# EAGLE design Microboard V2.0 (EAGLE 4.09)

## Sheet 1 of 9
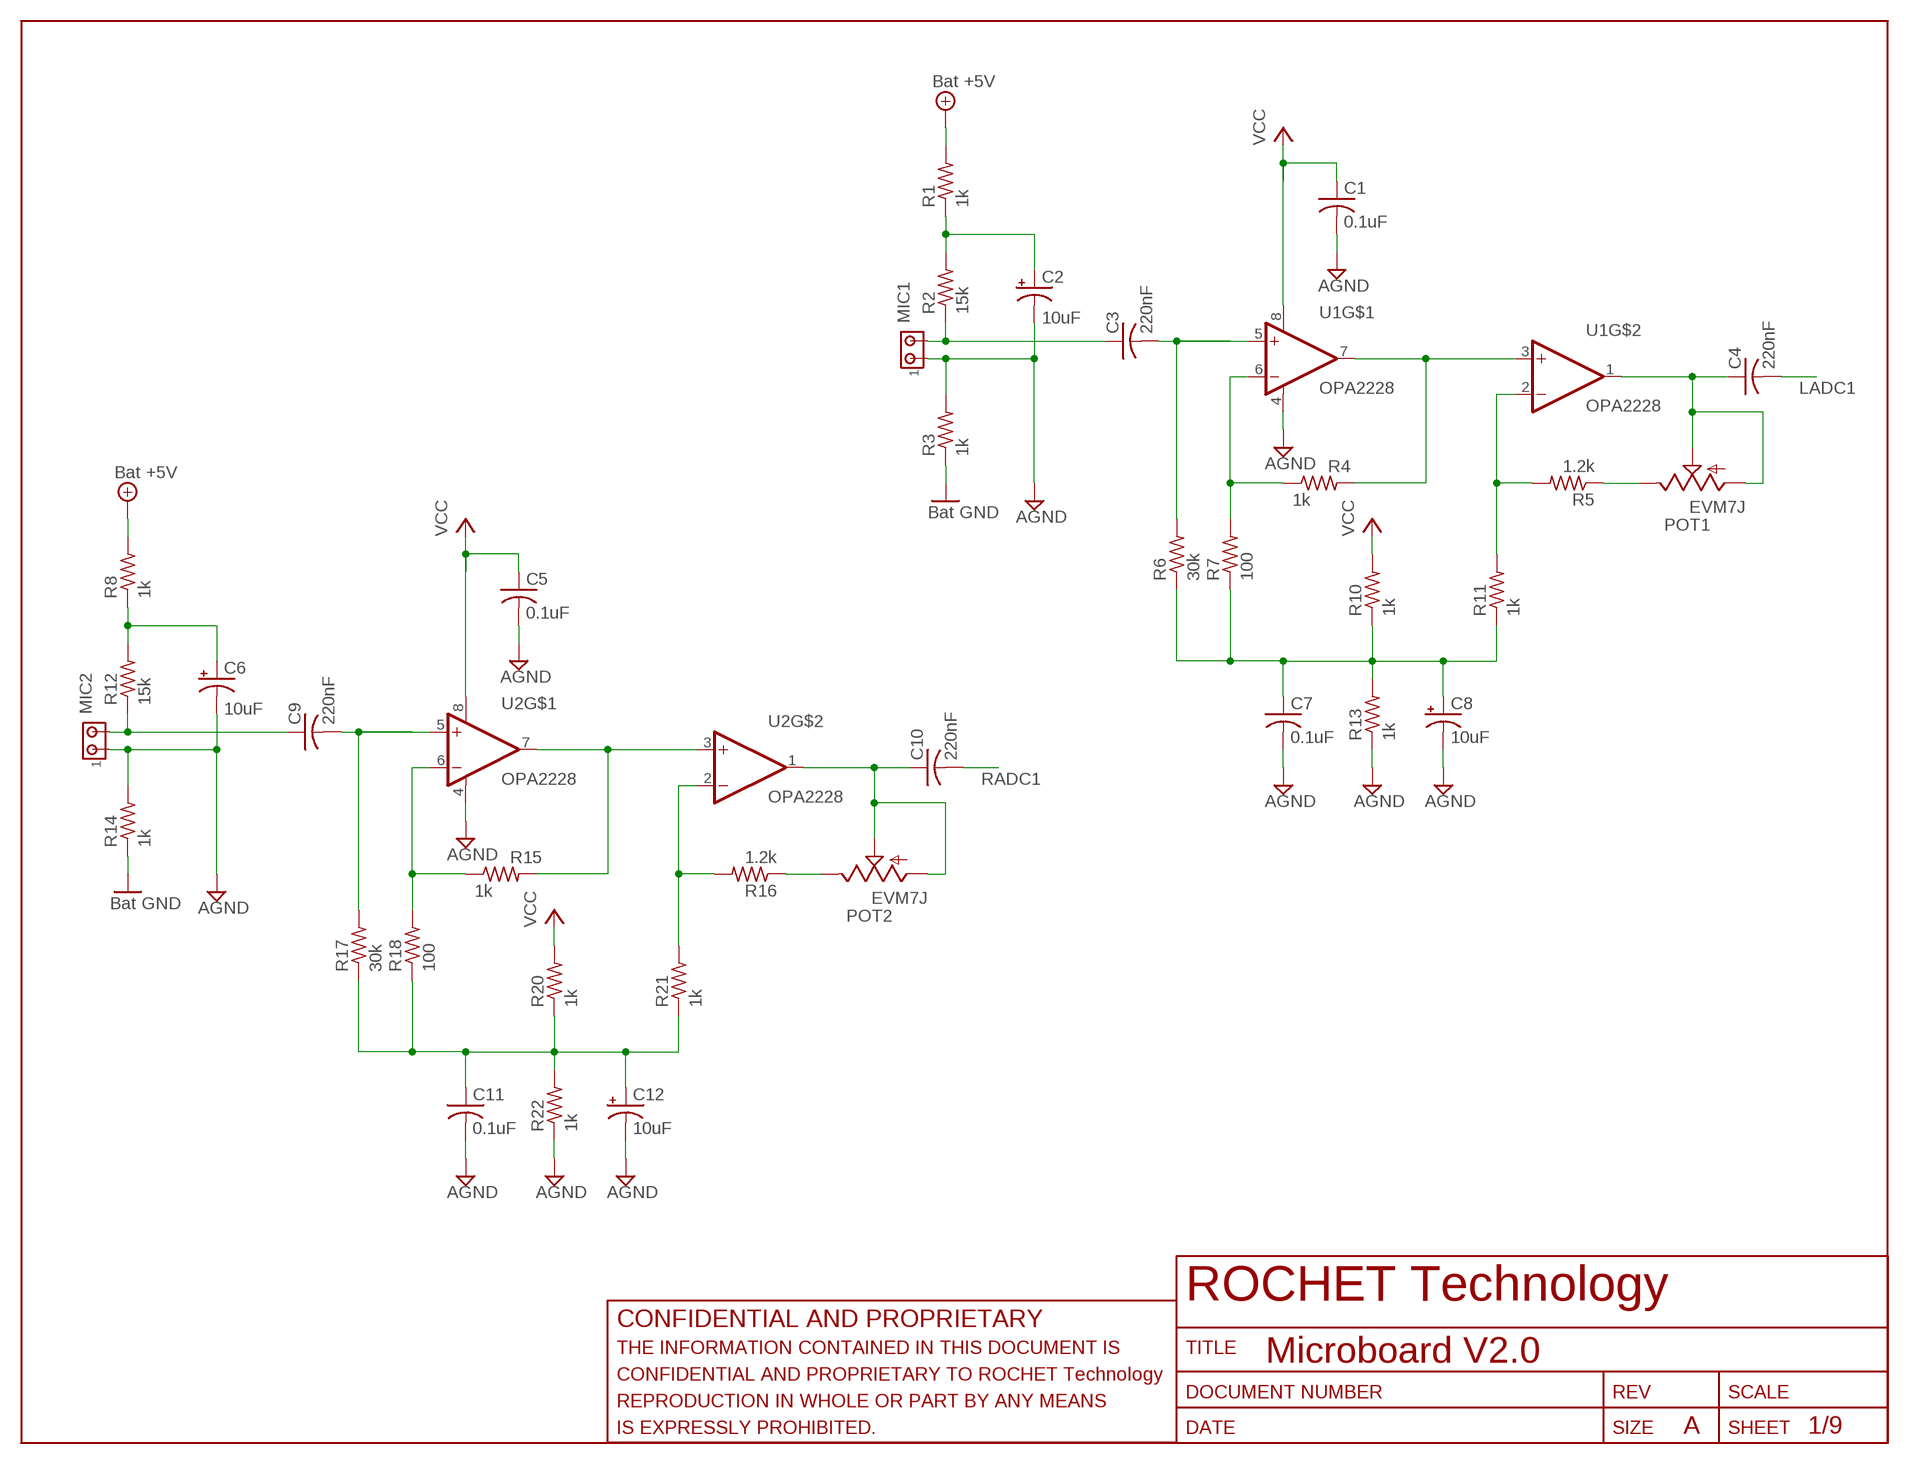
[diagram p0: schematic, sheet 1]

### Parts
C1  0.1uF  C-USC0603  [C0603]
C2  10uF  CPOL-USA/3216-18W  [A/3216-18W]
C3  220nF  C-US102-054X133  [C102-054X133]
C4  220nF  C-US102-054X133  [C102-054X133]
C5  0.1uF  C-USC0603  [C0603]
C6  10uF  CPOL-USA/3216-18W  [A/3216-18W]
C7  0.1uF  C-USC0603  [C0603]
C8  10uF  CPOL-USA/3216-18W  [A/3216-18W]
C9  220nF  C-US102-054X133  [C102-054X133]
C10  220nF  C-US102-054X133  [C102-054X133]
C11  0.1uF  C-USC0603  [C0603]
C12  10uF  CPOL-USA/3216-18W  [A/3216-18W]
MIC1  MTA02-100  [10X02MTA]
MIC2  MTA02-100  [10X02MTA]
POT1  EVM7J  P7J471CT-ND  [POT_EVM7J]
POT2  EVM7J  P7J471CT-ND  [POT_EVM7J]
R1  1k  R-US_M0805  [M0805]
R2  15k  R-US_M0805  [M0805]
R3  1k  R-US_M0805  [M0805]
R4  1k  R-US_R0805  [R0805]
R5  1.2k  R-US_R0805  [R0805]
R6  30k  R-US_R0805  [R0805]
R7  100  R-US_R0805  [R0805]
R8  1k  R-US_M0805  [M0805]
R10  1k  R-US_R0805  [R0805]
R11  1k  R-US_R0805  [R0805]
R12  15k  R-US_M0805  [M0805]
R13  1k  R-US_R0805  [R0805]
R14  1k  R-US_M0805  [M0805]
R15  1k  R-US_R0805  [R0805]
R16  1.2k  R-US_R0805  [R0805]
R17  30k  R-US_R0805  [R0805]
R18  100  R-US_R0805  [R0805]
R20  1k  R-US_R0805  [R0805]
R21  1k  R-US_R0805  [R0805]
R22  1k  R-US_R0805  [R0805]
U1  OPA2228  OPA2228SWAP  [SO-08]
U2  OPA2228  OPA2228SWAP  [SO-08]

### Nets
+5V: R1.2 R8.2 ; supply symbol labelled Bat +5V ; also sheet 3,5,7,9
AGND: C1.2 C2.- C5.2 C6.- C7.2 C8.- C11.2 C12.- MIC1.1 MIC2.1 R3.2 R13.1 R14.2 R22.1 U1.4(V-) U2.4(V-) ; also sheet 2,3,4,5,6,7,8,9
GND: R3.1 R14.1 ; supply symbol labelled Bat GND ; also sheet 3,5,7,9
LADC1: C4.2 ; also sheet 2
N$1: C9.1 MIC2.2 R12.1
N$2: C3.1 MIC1.2 R2.1
N$3: C9.2 R17.2 U2.5(+IN)
N$4: C3.2 R6.2 U1.5(+IN)
N$5: C11.1 C12.+ R17.1 R18.1 R20.1 R21.1 R22.2
N$6: C7.1 C8.+ R6.1 R7.1 R10.1 R11.1 R13.2
N$7: R15.1 R18.2 U2.6(-IN)
N$8: R15.2 U2.3(+IN) U2.7(OUT)
N$9: R16.2 R21.2 U2.2(-IN)
N$10: R4.1 R7.2 U1.6(-IN)
N$11: POT1.P$3(C) R5.1
N$12: R4.2 U1.3(+IN) U1.7(OUT)
N$13: R5.2 R11.2 U1.2(-IN)
N$15: C2.+ R1.1 R2.2
N$38: POT2.P$3(C) R16.1
N$58: C10.1 POT2.P$1(A) POT2.P$2(B) U2.1(OUT)
N$77: C4.1 POT1.P$1(A) POT1.P$2(B) U1.1(OUT)
N$78: C6.+ R8.1 R12.2
RADC1: C10.2 ; also sheet 2
VCC: C1.1 C5.1 R10.2 R20.2 U1.8(V+) U2.8(V+) ; also sheet 2,3,4,5,6,7,8,9

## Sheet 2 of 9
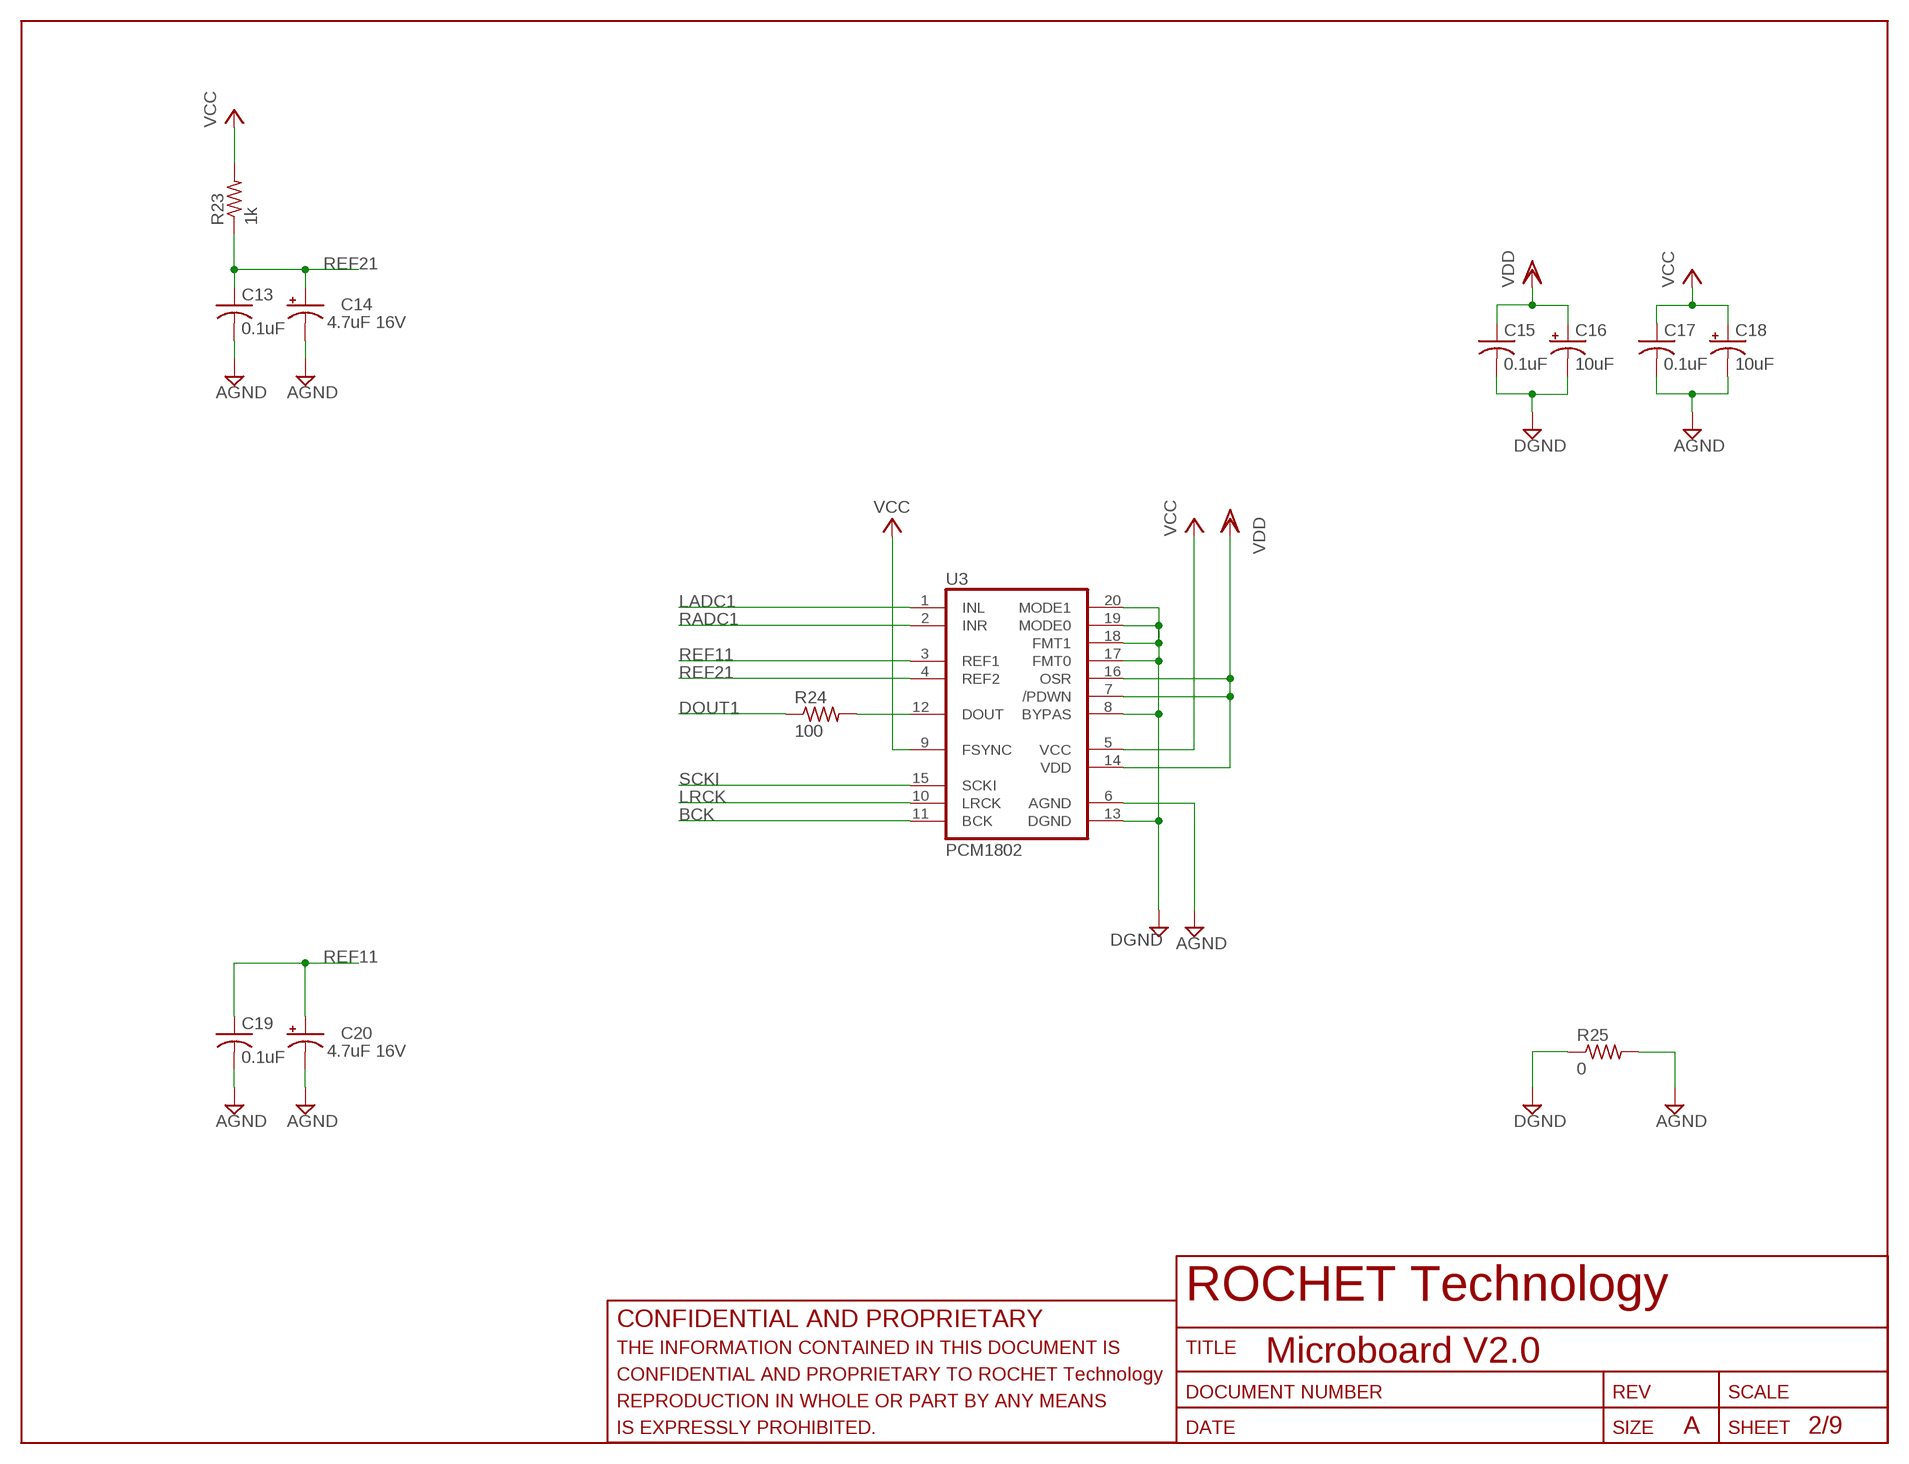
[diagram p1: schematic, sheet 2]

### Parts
C13  0.1uF  C-USC0603  [C0603]
C14  4.7uF 16V  CPOL-USA/3216-18W  [A/3216-18W]
C15  0.1uF  C-USC0603  [C0603]
C16  10uF  CPOL-USA/3216-18W  [A/3216-18W]
C17  0.1uF  C-USC0603  [C0603]
C18  10uF  CPOL-USA/3216-18W  [A/3216-18W]
C19  0.1uF  C-USC0603  [C0603]
C20  4.7uF 16V  CPOL-USA/3216-18W  [A/3216-18W]
R23  1k  R-US_R0805  [R0805]
R24  100  R-US_R0805  [R0805]
R25  0  R-US_R0805  [R0805]
U3  PCM1802  [SSOP20BU]

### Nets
AGND: C13.2 C14.- C17.2 C18.- C19.2 C20.- R25.2 U3.6(AGND) ; also sheet 1,3,4,5,6,7,8,9
BCK: U3.11(BCK) ; also sheet 4,6,8,9
DGND: C15.2 C16.- R25.1 U3.8(BYPAS) U3.13(DGND) U3.17(FMT0) U3.18(FMT1) U3.19(MODE0) U3.20(MODE1) ; also sheet 4,6,8,9
DOUT1: R24.1 ; also sheet 9
LADC1: U3.1(INL) ; also sheet 1
LRCK: U3.10(LRCK) ; also sheet 4,6,8,9
N$22: R24.2 U3.12(DOUT)
RADC1: U3.2(INR) ; also sheet 1
REF11: C19.1 C20.+ U3.3(REF1)
REF21: C13.1 C14.+ R23.1 U3.4(REF2)
SCKI: U3.15(SCKI) ; also sheet 4,6,8,9
VCC: C17.1 C18.+ R23.2 U3.5(VCC) U3.9(FSYNC) ; also sheet 1,3,4,5,6,7,8,9
VDD: C15.1 C16.+ U3.7(/PDWN) U3.14(VDD) U3.16(OSR) ; also sheet 4,6,8,9

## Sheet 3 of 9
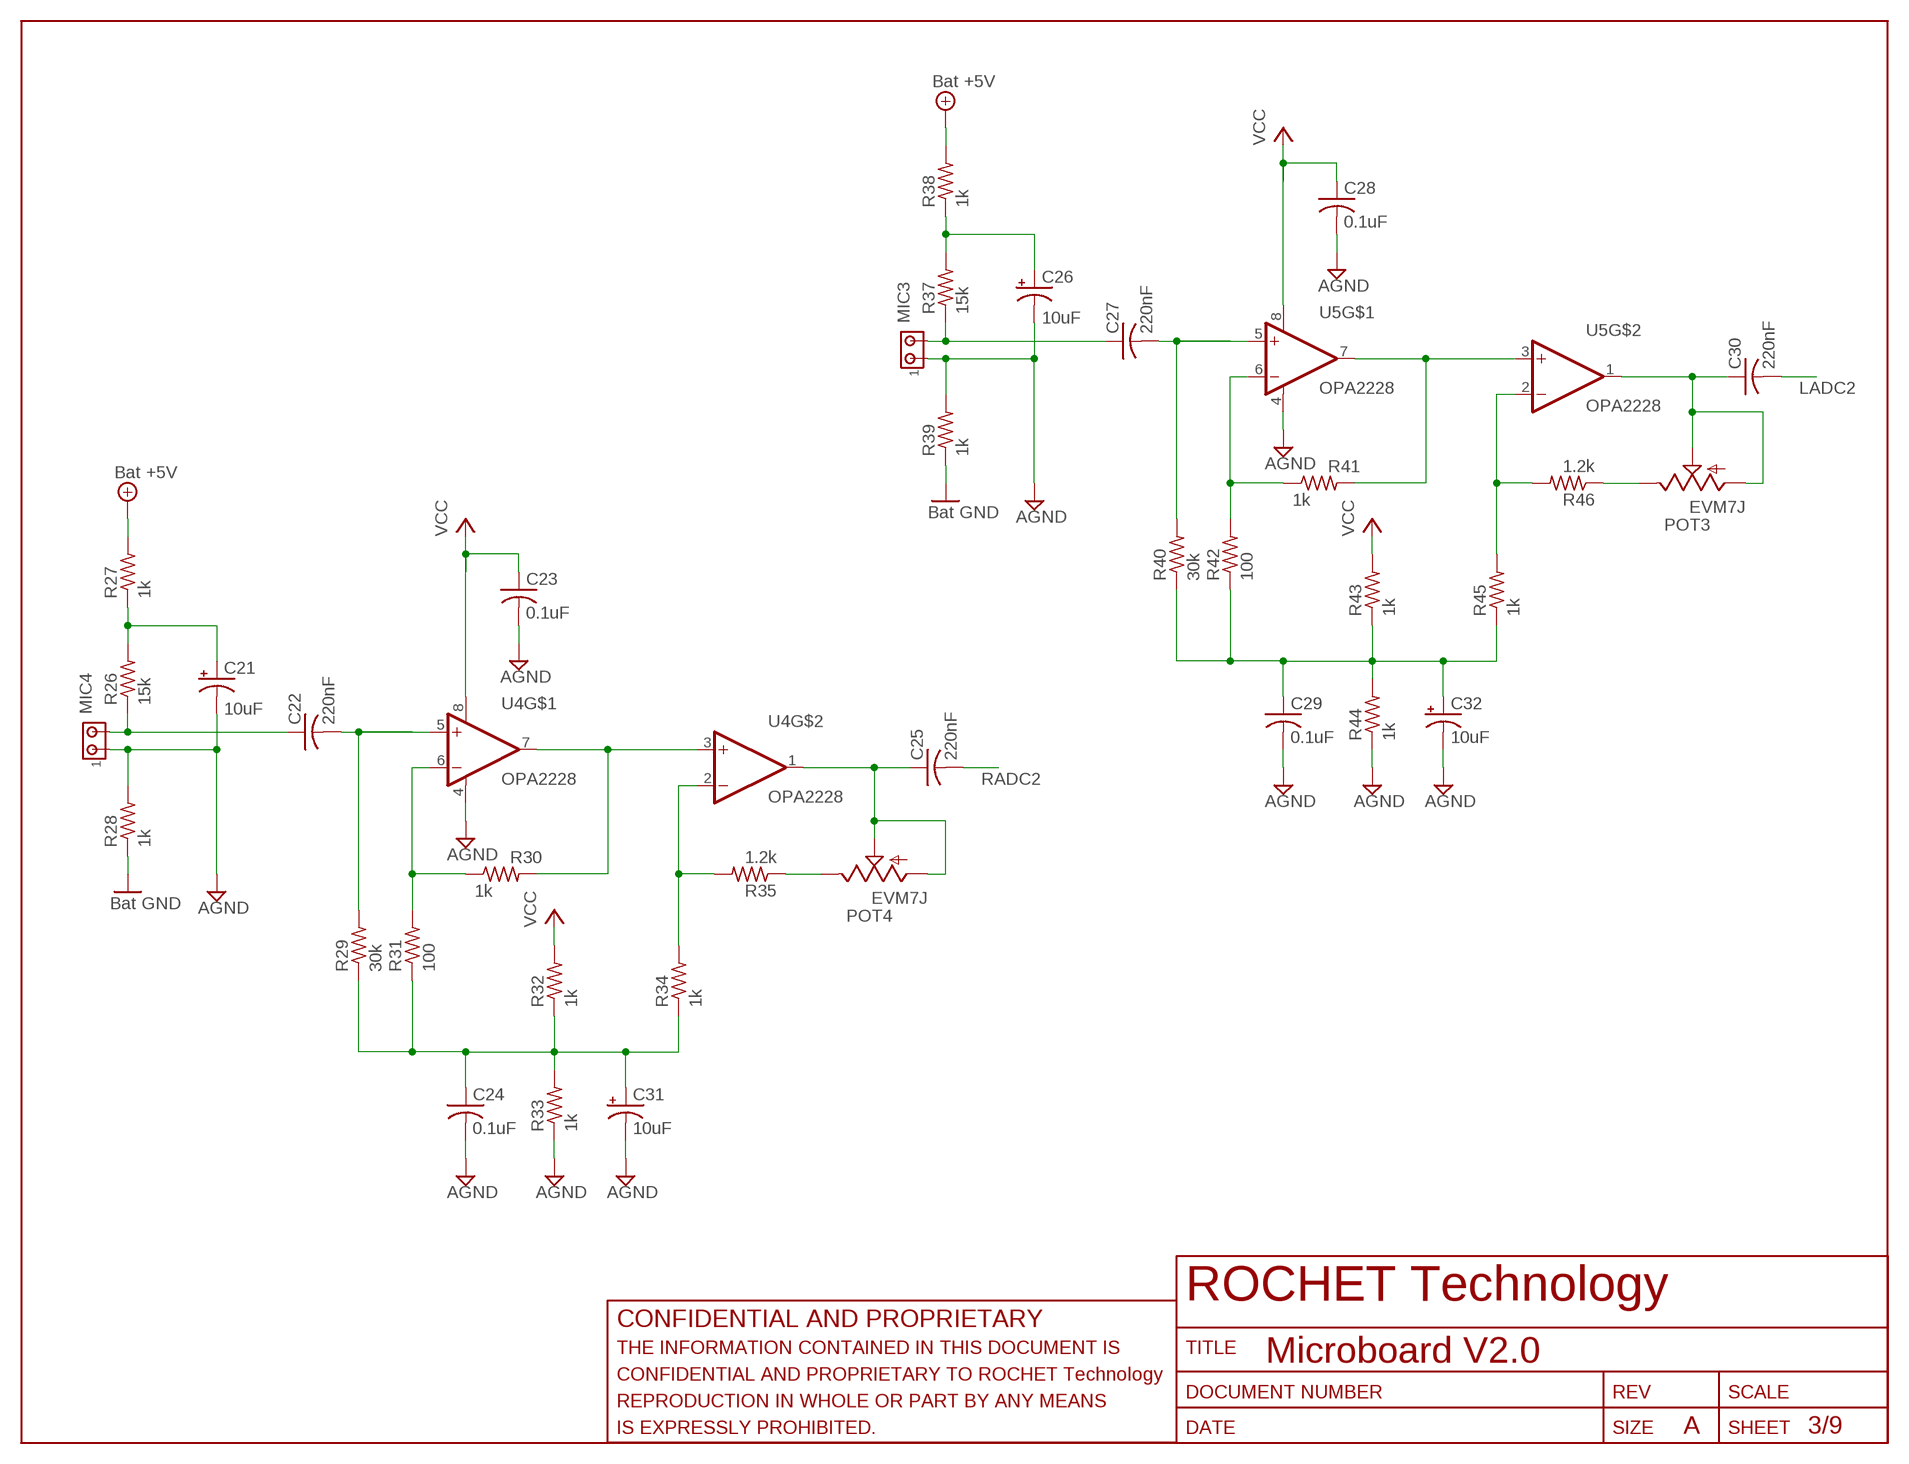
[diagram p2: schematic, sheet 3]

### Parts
C21  10uF  CPOL-USA/3216-18W  [A/3216-18W]
C22  220nF  C-US102-054X133  [C102-054X133]
C23  0.1uF  C-USC0603  [C0603]
C24  0.1uF  C-USC0603  [C0603]
C25  220nF  C-US102-054X133  [C102-054X133]
C26  10uF  CPOL-USA/3216-18W  [A/3216-18W]
C27  220nF  C-US102-054X133  [C102-054X133]
C28  0.1uF  C-USC0603  [C0603]
C29  0.1uF  C-USC0603  [C0603]
C30  220nF  C-US102-054X133  [C102-054X133]
C31  10uF  CPOL-USA/3216-18W  [A/3216-18W]
C32  10uF  CPOL-USA/3216-18W  [A/3216-18W]
MIC3  MTA02-100  [10X02MTA]
MIC4  MTA02-100  [10X02MTA]
POT3  EVM7J  P7J471CT-ND  [POT_EVM7J]
POT4  EVM7J  P7J471CT-ND  [POT_EVM7J]
R26  15k  R-US_M0805  [M0805]
R27  1k  R-US_M0805  [M0805]
R28  1k  R-US_M0805  [M0805]
R29  30k  R-US_R0805  [R0805]
R30  1k  R-US_R0805  [R0805]
R31  100  R-US_R0805  [R0805]
R32  1k  R-US_R0805  [R0805]
R33  1k  R-US_R0805  [R0805]
R34  1k  R-US_R0805  [R0805]
R35  1.2k  R-US_R0805  [R0805]
R37  15k  R-US_M0805  [M0805]
R38  1k  R-US_M0805  [M0805]
R39  1k  R-US_M0805  [M0805]
R40  30k  R-US_R0805  [R0805]
R41  1k  R-US_R0805  [R0805]
R42  100  R-US_R0805  [R0805]
R43  1k  R-US_R0805  [R0805]
R44  1k  R-US_R0805  [R0805]
R45  1k  R-US_R0805  [R0805]
R46  1.2k  R-US_R0805  [R0805]
U4  OPA2228  OPA2228SWAP  [SO-08]
U5  OPA2228  OPA2228SWAP  [SO-08]

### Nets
+5V: R27.2 R38.2 ; supply symbol labelled Bat +5V ; also sheet 1,5,7,9
AGND: C21.- C23.2 C24.2 C26.- C28.2 C29.2 C31.- C32.- MIC3.1 MIC4.1 R28.2 R33.1 R39.2 R44.1 U4.4(V-) U5.4(V-) ; also sheet 1,2,4,5,6,7,8,9
GND: R28.1 R39.1 ; supply symbol labelled Bat GND ; also sheet 1,5,7,9
LADC2: C30.2 ; also sheet 4
N$14: POT4.P$3(C) R35.1
N$16: C22.1 MIC4.2 R26.1
N$18: C22.2 R29.2 U4.5(+IN)
N$19: C24.1 C31.+ R29.1 R31.1 R32.1 R33.2 R34.1
N$21: R30.1 R31.2 U4.6(-IN)
N$23: R30.2 U4.3(+IN) U4.7(OUT)
N$24: R34.2 R35.2 U4.2(-IN)
N$25: POT3.P$3(C) R46.1
N$26: C21.+ R26.2 R27.1
N$27: C27.1 MIC3.2 R37.1
N$28: C27.2 R40.2 U5.5(+IN)
N$29: C29.1 C32.+ R40.1 R42.1 R43.1 R44.2 R45.1
N$30: R41.1 R42.2 U5.6(-IN)
N$31: R41.2 U5.3(+IN) U5.7(OUT)
N$32: R45.2 R46.2 U5.2(-IN)
N$34: C26.+ R37.2 R38.1
N$81: C25.1 POT4.P$1(A) POT4.P$2(B) U4.1(OUT)
N$82: C30.1 POT3.P$1(A) POT3.P$2(B) U5.1(OUT)
RADC2: C25.2 ; also sheet 4
VCC: C23.1 C28.1 R32.2 R43.2 U4.8(V+) U5.8(V+) ; also sheet 1,2,4,5,6,7,8,9

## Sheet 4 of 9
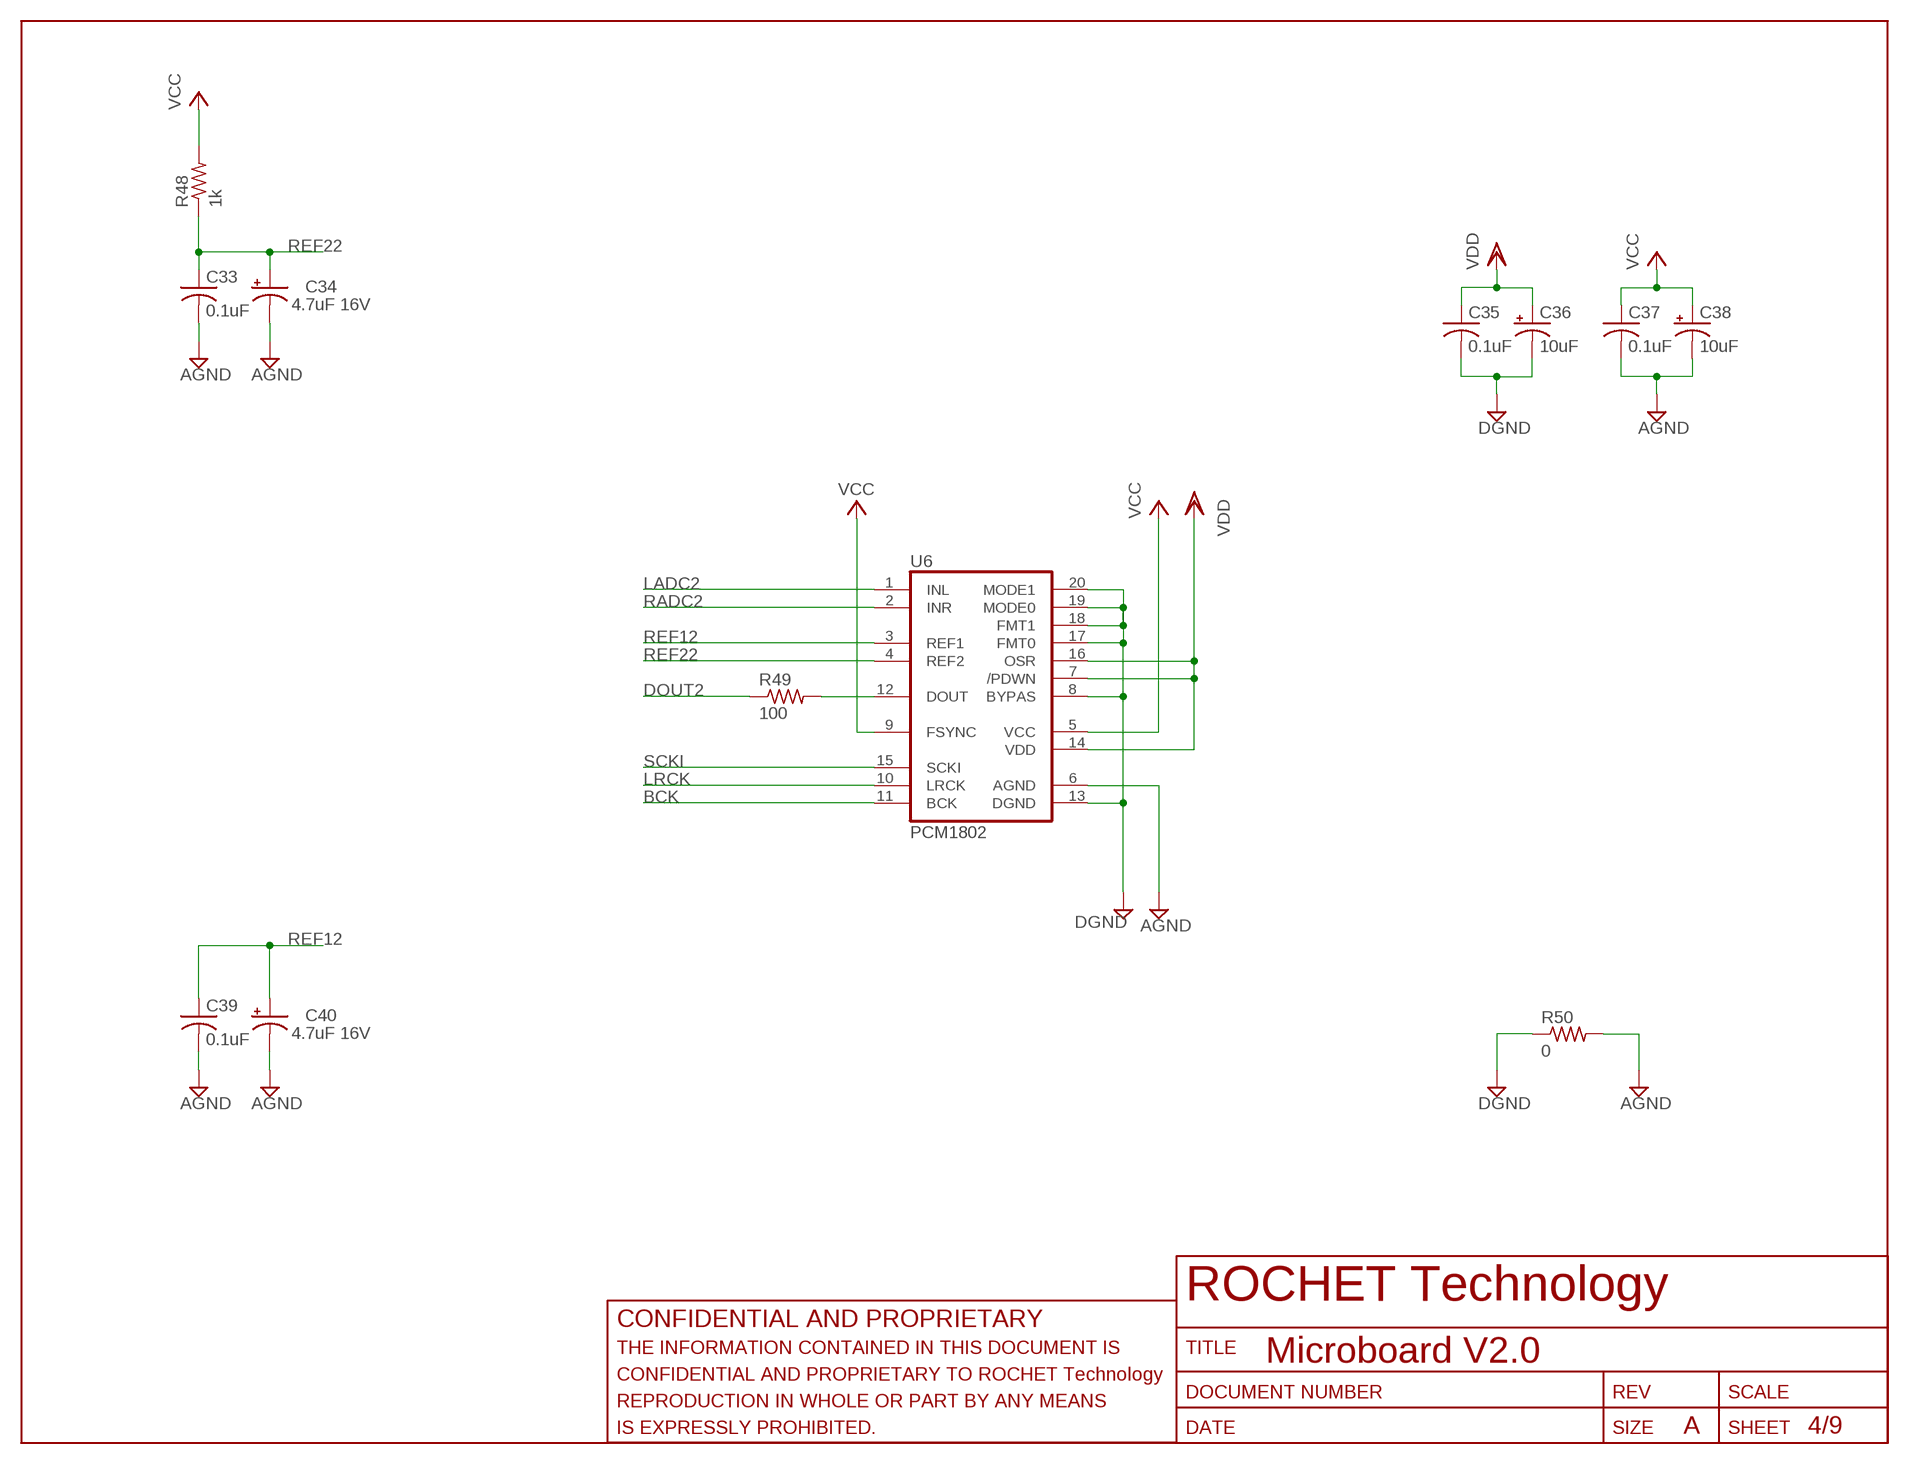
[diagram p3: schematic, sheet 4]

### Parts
C33  0.1uF  C-USC0603  [C0603]
C34  4.7uF 16V  CPOL-USA/3216-18W  [A/3216-18W]
C35  0.1uF  C-USC0603  [C0603]
C36  10uF  CPOL-USA/3216-18W  [A/3216-18W]
C37  0.1uF  C-USC0603  [C0603]
C38  10uF  CPOL-USA/3216-18W  [A/3216-18W]
C39  0.1uF  C-USC0603  [C0603]
C40  4.7uF 16V  CPOL-USA/3216-18W  [A/3216-18W]
R48  1k  R-US_R0805  [R0805]
R49  100  R-US_R0805  [R0805]
R50  0  R-US_R0805  [R0805]
U6  PCM1802  [SSOP20BU]

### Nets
AGND: C33.2 C34.- C37.2 C38.- C39.2 C40.- R50.2 U6.6(AGND) ; also sheet 1,2,3,5,6,7,8,9
BCK: U6.11(BCK) ; also sheet 2,6,8,9
DGND: C35.2 C36.- R50.1 U6.8(BYPAS) U6.13(DGND) U6.17(FMT0) U6.18(FMT1) U6.19(MODE0) U6.20(MODE1) ; also sheet 2,6,8,9
DOUT2: R49.1 ; also sheet 9
LADC2: U6.1(INL) ; also sheet 3
LRCK: U6.10(LRCK) ; also sheet 2,6,8,9
N$17: R49.2 U6.12(DOUT)
RADC2: U6.2(INR) ; also sheet 3
REF12: C39.1 C40.+ U6.3(REF1)
REF22: C33.1 C34.+ R48.1 U6.4(REF2)
SCKI: U6.15(SCKI) ; also sheet 2,6,8,9
VCC: C37.1 C38.+ R48.2 U6.5(VCC) U6.9(FSYNC) ; also sheet 1,2,3,5,6,7,8,9
VDD: C35.1 C36.+ U6.7(/PDWN) U6.14(VDD) U6.16(OSR) ; also sheet 2,6,8,9

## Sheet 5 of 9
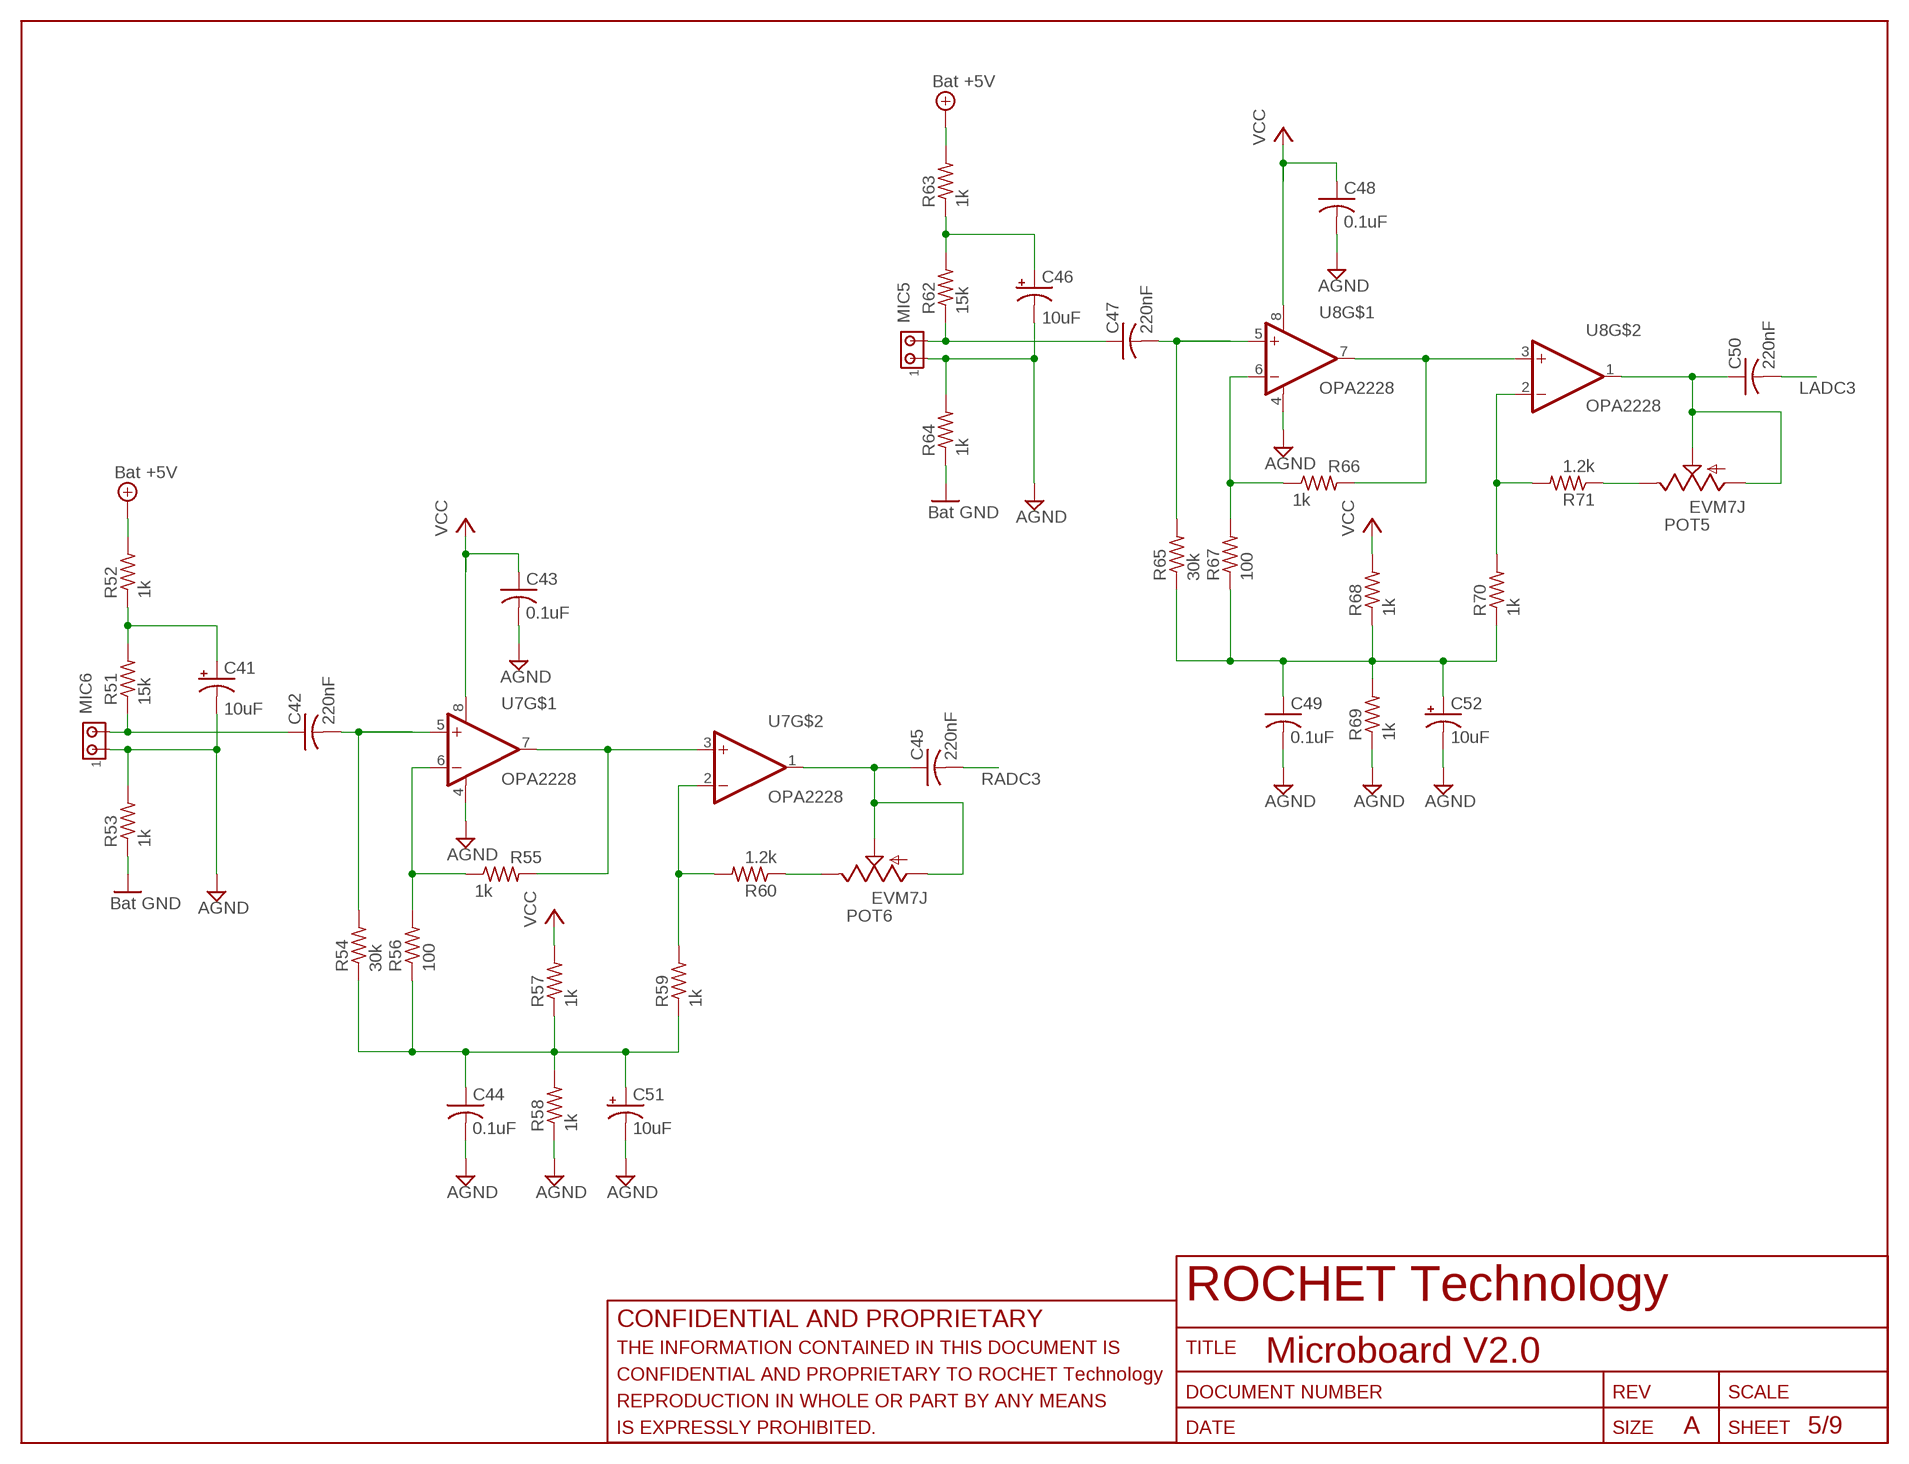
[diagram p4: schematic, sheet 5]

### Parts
C41  10uF  CPOL-USA/3216-18W  [A/3216-18W]
C42  220nF  C-US102-054X133  [C102-054X133]
C43  0.1uF  C-USC0603  [C0603]
C44  0.1uF  C-USC0603  [C0603]
C45  220nF  C-US102-054X133  [C102-054X133]
C46  10uF  CPOL-USA/3216-18W  [A/3216-18W]
C47  220nF  C-US102-054X133  [C102-054X133]
C48  0.1uF  C-USC0603  [C0603]
C49  0.1uF  C-USC0603  [C0603]
C50  220nF  C-US102-054X133  [C102-054X133]
C51  10uF  CPOL-USA/3216-18W  [A/3216-18W]
C52  10uF  CPOL-USA/3216-18W  [A/3216-18W]
MIC5  MTA02-100  [10X02MTA]
MIC6  MTA02-100  [10X02MTA]
POT5  EVM7J  P7J471CT-ND  [POT_EVM7J]
POT6  EVM7J  P7J471CT-ND  [POT_EVM7J]
R51  15k  R-US_M0805  [M0805]
R52  1k  R-US_M0805  [M0805]
R53  1k  R-US_M0805  [M0805]
R54  30k  R-US_R0805  [R0805]
R55  1k  R-US_R0805  [R0805]
R56  100  R-US_R0805  [R0805]
R57  1k  R-US_R0805  [R0805]
R58  1k  R-US_R0805  [R0805]
R59  1k  R-US_R0805  [R0805]
R60  1.2k  R-US_R0805  [R0805]
R62  15k  R-US_M0805  [M0805]
R63  1k  R-US_M0805  [M0805]
R64  1k  R-US_M0805  [M0805]
R65  30k  R-US_R0805  [R0805]
R66  1k  R-US_R0805  [R0805]
R67  100  R-US_R0805  [R0805]
R68  1k  R-US_R0805  [R0805]
R69  1k  R-US_R0805  [R0805]
R70  1k  R-US_R0805  [R0805]
R71  1.2k  R-US_R0805  [R0805]
U7  OPA2228  OPA2228SWAP  [SO-08]
U8  OPA2228  OPA2228SWAP  [SO-08]

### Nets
+5V: R52.2 R63.2 ; supply symbol labelled Bat +5V ; also sheet 1,3,7,9
AGND: C41.- C43.2 C44.2 C46.- C48.2 C49.2 C51.- C52.- MIC5.1 MIC6.1 R53.2 R58.1 R64.2 R69.1 U7.4(V-) U8.4(V-) ; also sheet 1,2,3,4,6,7,8,9
GND: R53.1 R64.1 ; supply symbol labelled Bat GND ; also sheet 1,3,7,9
LADC3: C50.2 ; also sheet 6
N$33: POT6.P$3(C) R60.1
N$39: C42.1 MIC6.2 R51.1
N$40: C42.2 R54.2 U7.5(+IN)
N$41: C44.1 C51.+ R54.1 R56.1 R57.1 R58.2 R59.1
N$42: R55.1 R56.2 U7.6(-IN)
N$43: R55.2 U7.3(+IN) U7.7(OUT)
N$44: R59.2 R60.2 U7.2(-IN)
N$45: POT5.P$3(C) R71.1
N$46: C41.+ R51.2 R52.1
N$47: C47.1 MIC5.2 R62.1
N$48: C47.2 R65.2 U8.5(+IN)
N$49: C49.1 C52.+ R65.1 R67.1 R68.1 R69.2 R70.1
N$50: R66.1 R67.2 U8.6(-IN)
N$51: R66.2 U8.3(+IN) U8.7(OUT)
N$52: R70.2 R71.2 U8.2(-IN)
N$54: C46.+ R62.2 R63.1
N$83: C45.1 POT6.P$1(A) POT6.P$2(B) U7.1(OUT)
N$84: C50.1 POT5.P$1(A) POT5.P$2(B) U8.1(OUT)
RADC3: C45.2 ; also sheet 6
VCC: C43.1 C48.1 R57.2 R68.2 U7.8(V+) U8.8(V+) ; also sheet 1,2,3,4,6,7,8,9

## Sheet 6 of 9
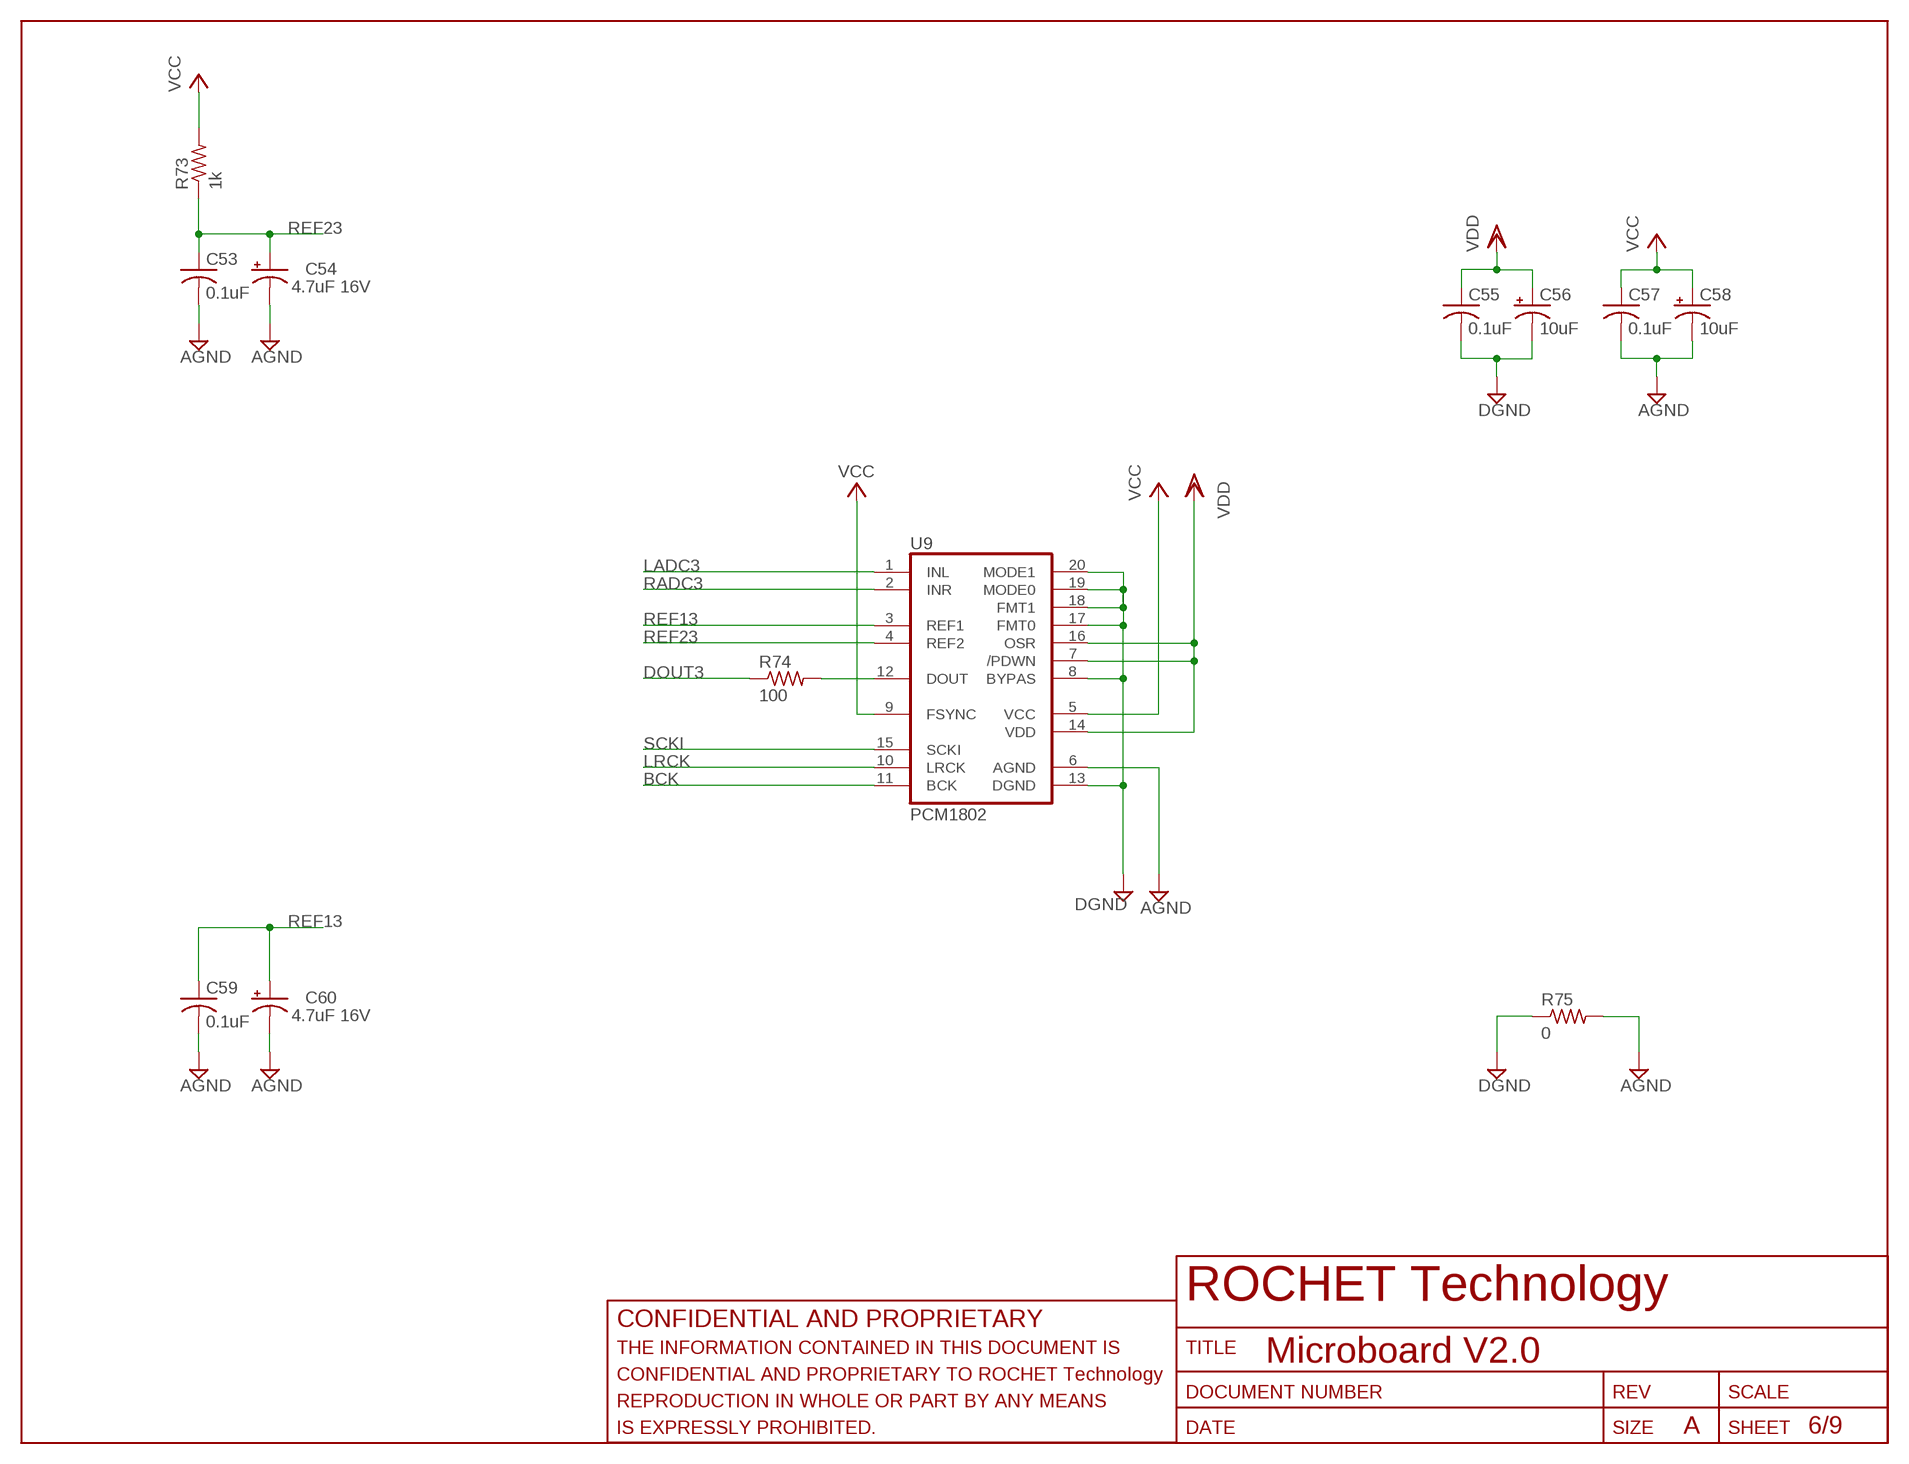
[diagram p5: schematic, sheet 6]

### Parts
C53  0.1uF  C-USC0603  [C0603]
C54  4.7uF 16V  CPOL-USA/3216-18W  [A/3216-18W]
C55  0.1uF  C-USC0603  [C0603]
C56  10uF  CPOL-USA/3216-18W  [A/3216-18W]
C57  0.1uF  C-USC0603  [C0603]
C58  10uF  CPOL-USA/3216-18W  [A/3216-18W]
C59  0.1uF  C-USC0603  [C0603]
C60  4.7uF 16V  CPOL-USA/3216-18W  [A/3216-18W]
R73  1k  R-US_R0805  [R0805]
R74  100  R-US_R0805  [R0805]
R75  0  R-US_R0805  [R0805]
U9  PCM1802  [SSOP20BU]

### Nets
AGND: C53.2 C54.- C57.2 C58.- C59.2 C60.- R75.2 U9.6(AGND) ; also sheet 1,2,3,4,5,7,8,9
BCK: U9.11(BCK) ; also sheet 2,4,8,9
DGND: C55.2 C56.- R75.1 U9.8(BYPAS) U9.13(DGND) U9.17(FMT0) U9.18(FMT1) U9.19(MODE0) U9.20(MODE1) ; also sheet 2,4,8,9
DOUT3: R74.1 ; also sheet 9
LADC3: U9.1(INL) ; also sheet 5
LRCK: U9.10(LRCK) ; also sheet 2,4,8,9
N$20: R74.2 U9.12(DOUT)
RADC3: U9.2(INR) ; also sheet 5
REF13: C59.1 C60.+ U9.3(REF1)
REF23: C53.1 C54.+ R73.1 U9.4(REF2)
SCKI: U9.15(SCKI) ; also sheet 2,4,8,9
VCC: C57.1 C58.+ R73.2 U9.5(VCC) U9.9(FSYNC) ; also sheet 1,2,3,4,5,7,8,9
VDD: C55.1 C56.+ U9.7(/PDWN) U9.14(VDD) U9.16(OSR) ; also sheet 2,4,8,9

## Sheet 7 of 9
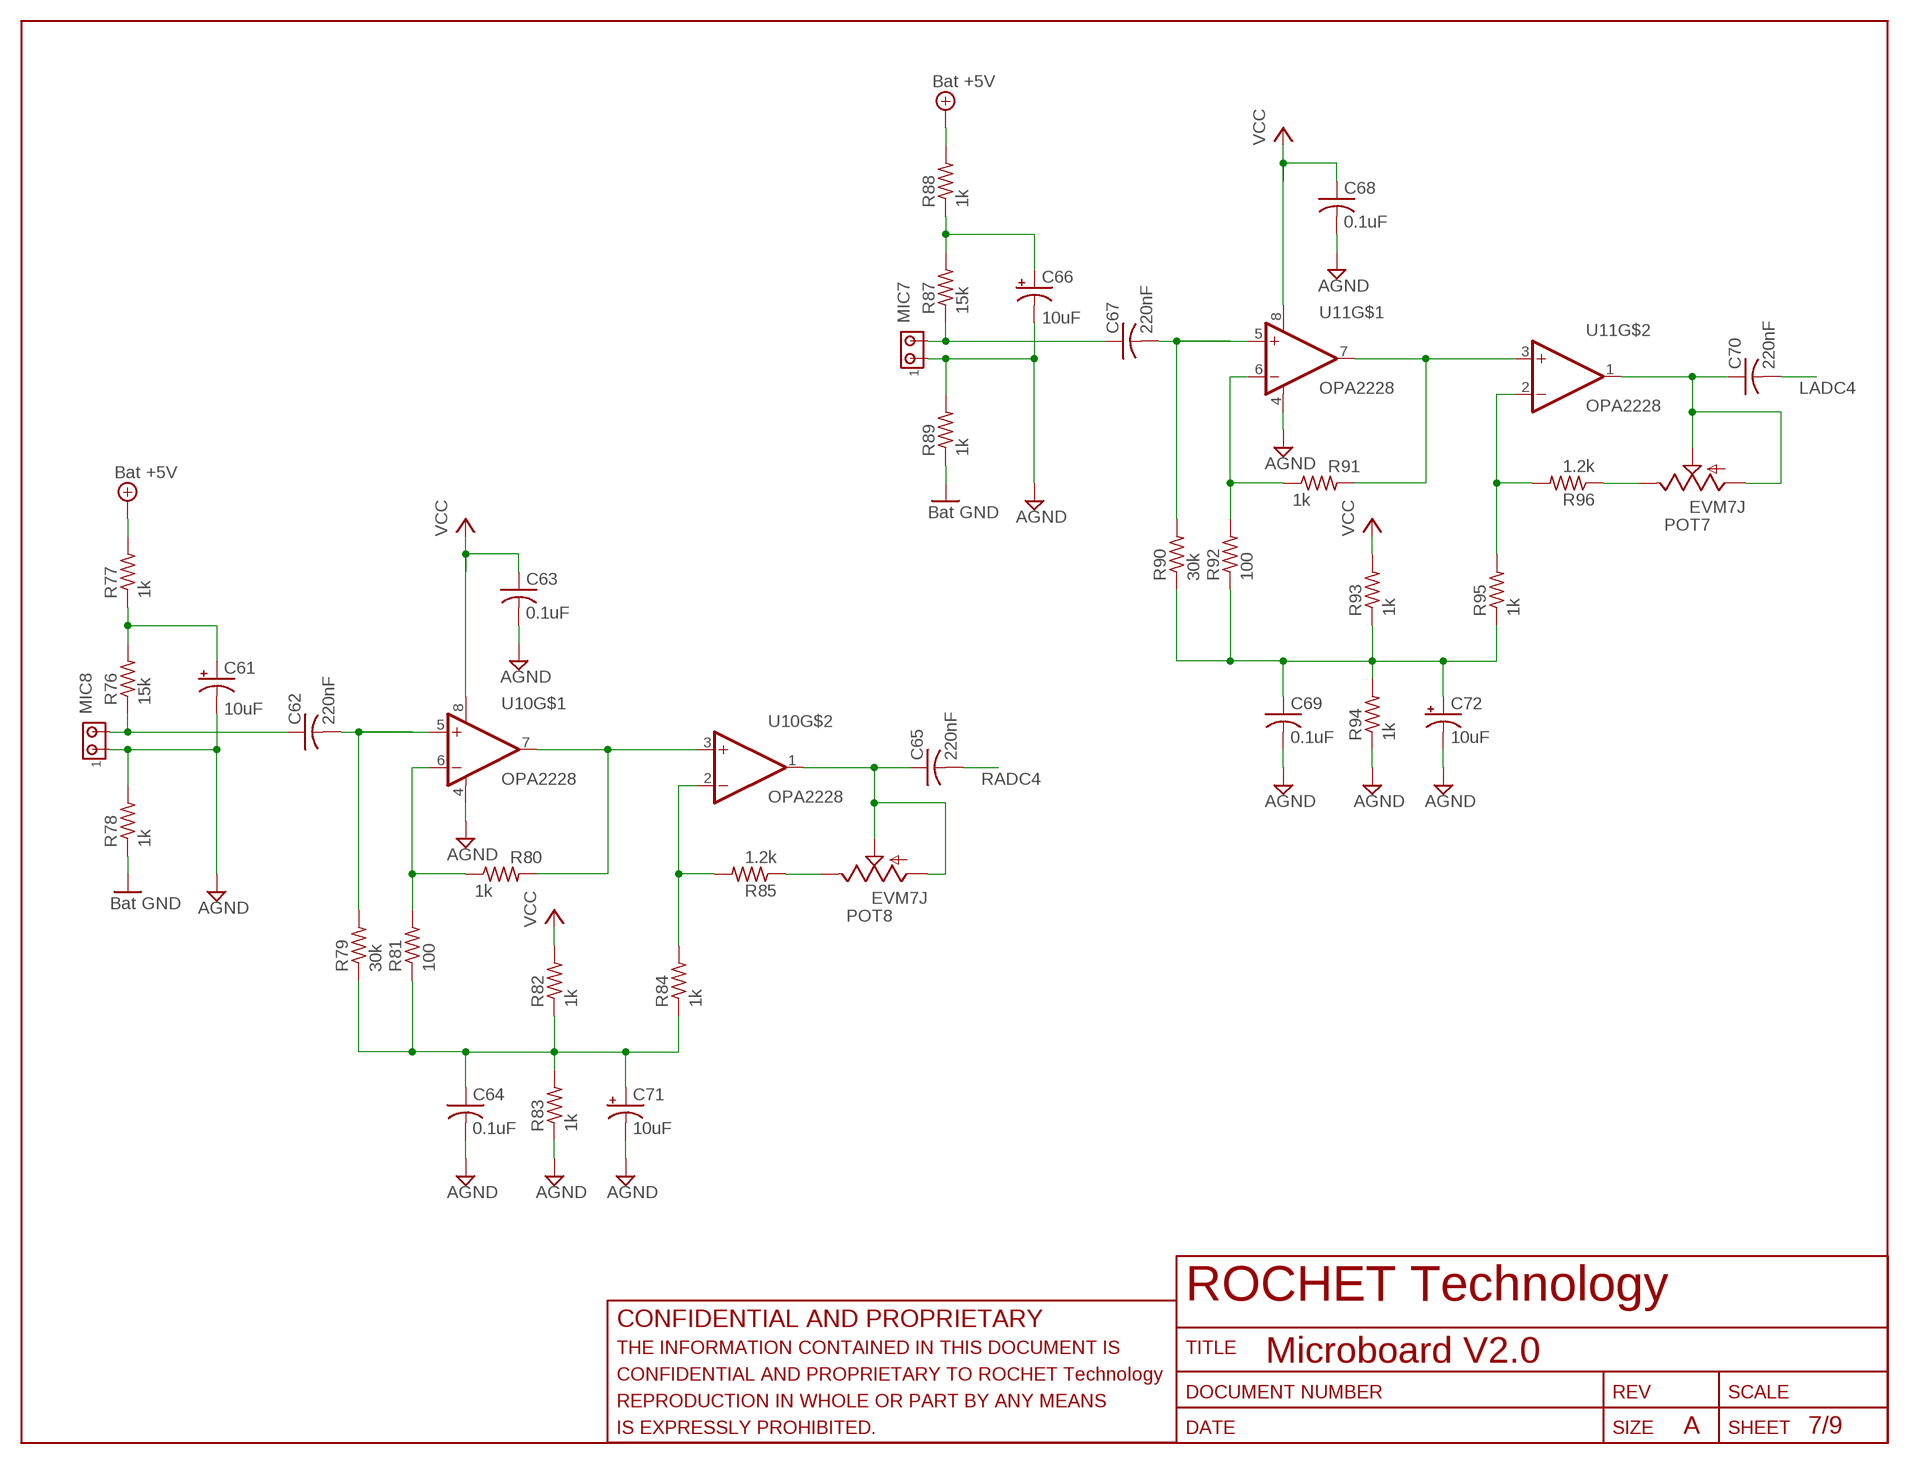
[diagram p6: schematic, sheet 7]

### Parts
C61  10uF  CPOL-USA/3216-18W  [A/3216-18W]
C62  220nF  C-US102-054X133  [C102-054X133]
C63  0.1uF  C-USC0603  [C0603]
C64  0.1uF  C-USC0603  [C0603]
C65  220nF  C-US102-054X133  [C102-054X133]
C66  10uF  CPOL-USA/3216-18W  [A/3216-18W]
C67  220nF  C-US102-054X133  [C102-054X133]
C68  0.1uF  C-USC0603  [C0603]
C69  0.1uF  C-USC0603  [C0603]
C70  220nF  C-US102-054X133  [C102-054X133]
C71  10uF  CPOL-USA/3216-18W  [A/3216-18W]
C72  10uF  CPOL-USA/3216-18W  [A/3216-18W]
MIC7  MTA02-100  [10X02MTA]
MIC8  MTA02-100  [10X02MTA]
POT7  EVM7J  P7J471CT-ND  [POT_EVM7J]
POT8  EVM7J  P7J471CT-ND  [POT_EVM7J]
R76  15k  R-US_M0805  [M0805]
R77  1k  R-US_M0805  [M0805]
R78  1k  R-US_M0805  [M0805]
R79  30k  R-US_R0805  [R0805]
R80  1k  R-US_R0805  [R0805]
R81  100  R-US_R0805  [R0805]
R82  1k  R-US_R0805  [R0805]
R83  1k  R-US_R0805  [R0805]
R84  1k  R-US_R0805  [R0805]
R85  1.2k  R-US_R0805  [R0805]
R87  15k  R-US_M0805  [M0805]
R88  1k  R-US_M0805  [M0805]
R89  1k  R-US_M0805  [M0805]
R90  30k  R-US_R0805  [R0805]
R91  1k  R-US_R0805  [R0805]
R92  100  R-US_R0805  [R0805]
R93  1k  R-US_R0805  [R0805]
R94  1k  R-US_R0805  [R0805]
R95  1k  R-US_R0805  [R0805]
R96  1.2k  R-US_R0805  [R0805]
U10  OPA2228  OPA2228SWAP  [SO-08]
U11  OPA2228  OPA2228SWAP  [SO-08]

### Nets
+5V: R77.2 R88.2 ; supply symbol labelled Bat +5V ; also sheet 1,3,5,9
AGND: C61.- C63.2 C64.2 C66.- C68.2 C69.2 C71.- C72.- MIC7.1 MIC8.1 R78.2 R83.1 R89.2 R94.1 U10.4(V-) U11.4(V-) ; also sheet 1,2,3,4,5,6,8,9
GND: R78.1 R89.1 ; supply symbol labelled Bat GND ; also sheet 1,3,5,9
LADC4: C70.2 ; also sheet 8
N$53: POT8.P$3(C) R85.1
N$59: C62.1 MIC8.2 R76.1
N$60: C62.2 R79.2 U10.5(+IN)
N$61: C64.1 C71.+ R79.1 R81.1 R82.1 R83.2 R84.1
N$62: R80.1 R81.2 U10.6(-IN)
N$63: R80.2 U10.3(+IN) U10.7(OUT)
N$64: R84.2 R85.2 U10.2(-IN)
N$66: C61.+ R76.2 R77.1
N$67: C67.1 MIC7.2 R87.1
N$68: C67.2 R90.2 U11.5(+IN)
N$69: C69.1 C72.+ R90.1 R92.1 R93.1 R94.2 R95.1
N$70: R91.1 R92.2 U11.6(-IN)
N$71: R91.2 U11.3(+IN) U11.7(OUT)
N$72: R95.2 R96.2 U11.2(-IN)
N$74: C66.+ R87.2 R88.1
N$85: POT7.P$3(C) R96.1
N$86: C65.1 POT8.P$1(A) POT8.P$2(B) U10.1(OUT)
N$87: C70.1 POT7.P$1(A) POT7.P$2(B) U11.1(OUT)
RADC4: C65.2 ; also sheet 8
VCC: C63.1 C68.1 R82.2 R93.2 U10.8(V+) U11.8(V+) ; also sheet 1,2,3,4,5,6,8,9

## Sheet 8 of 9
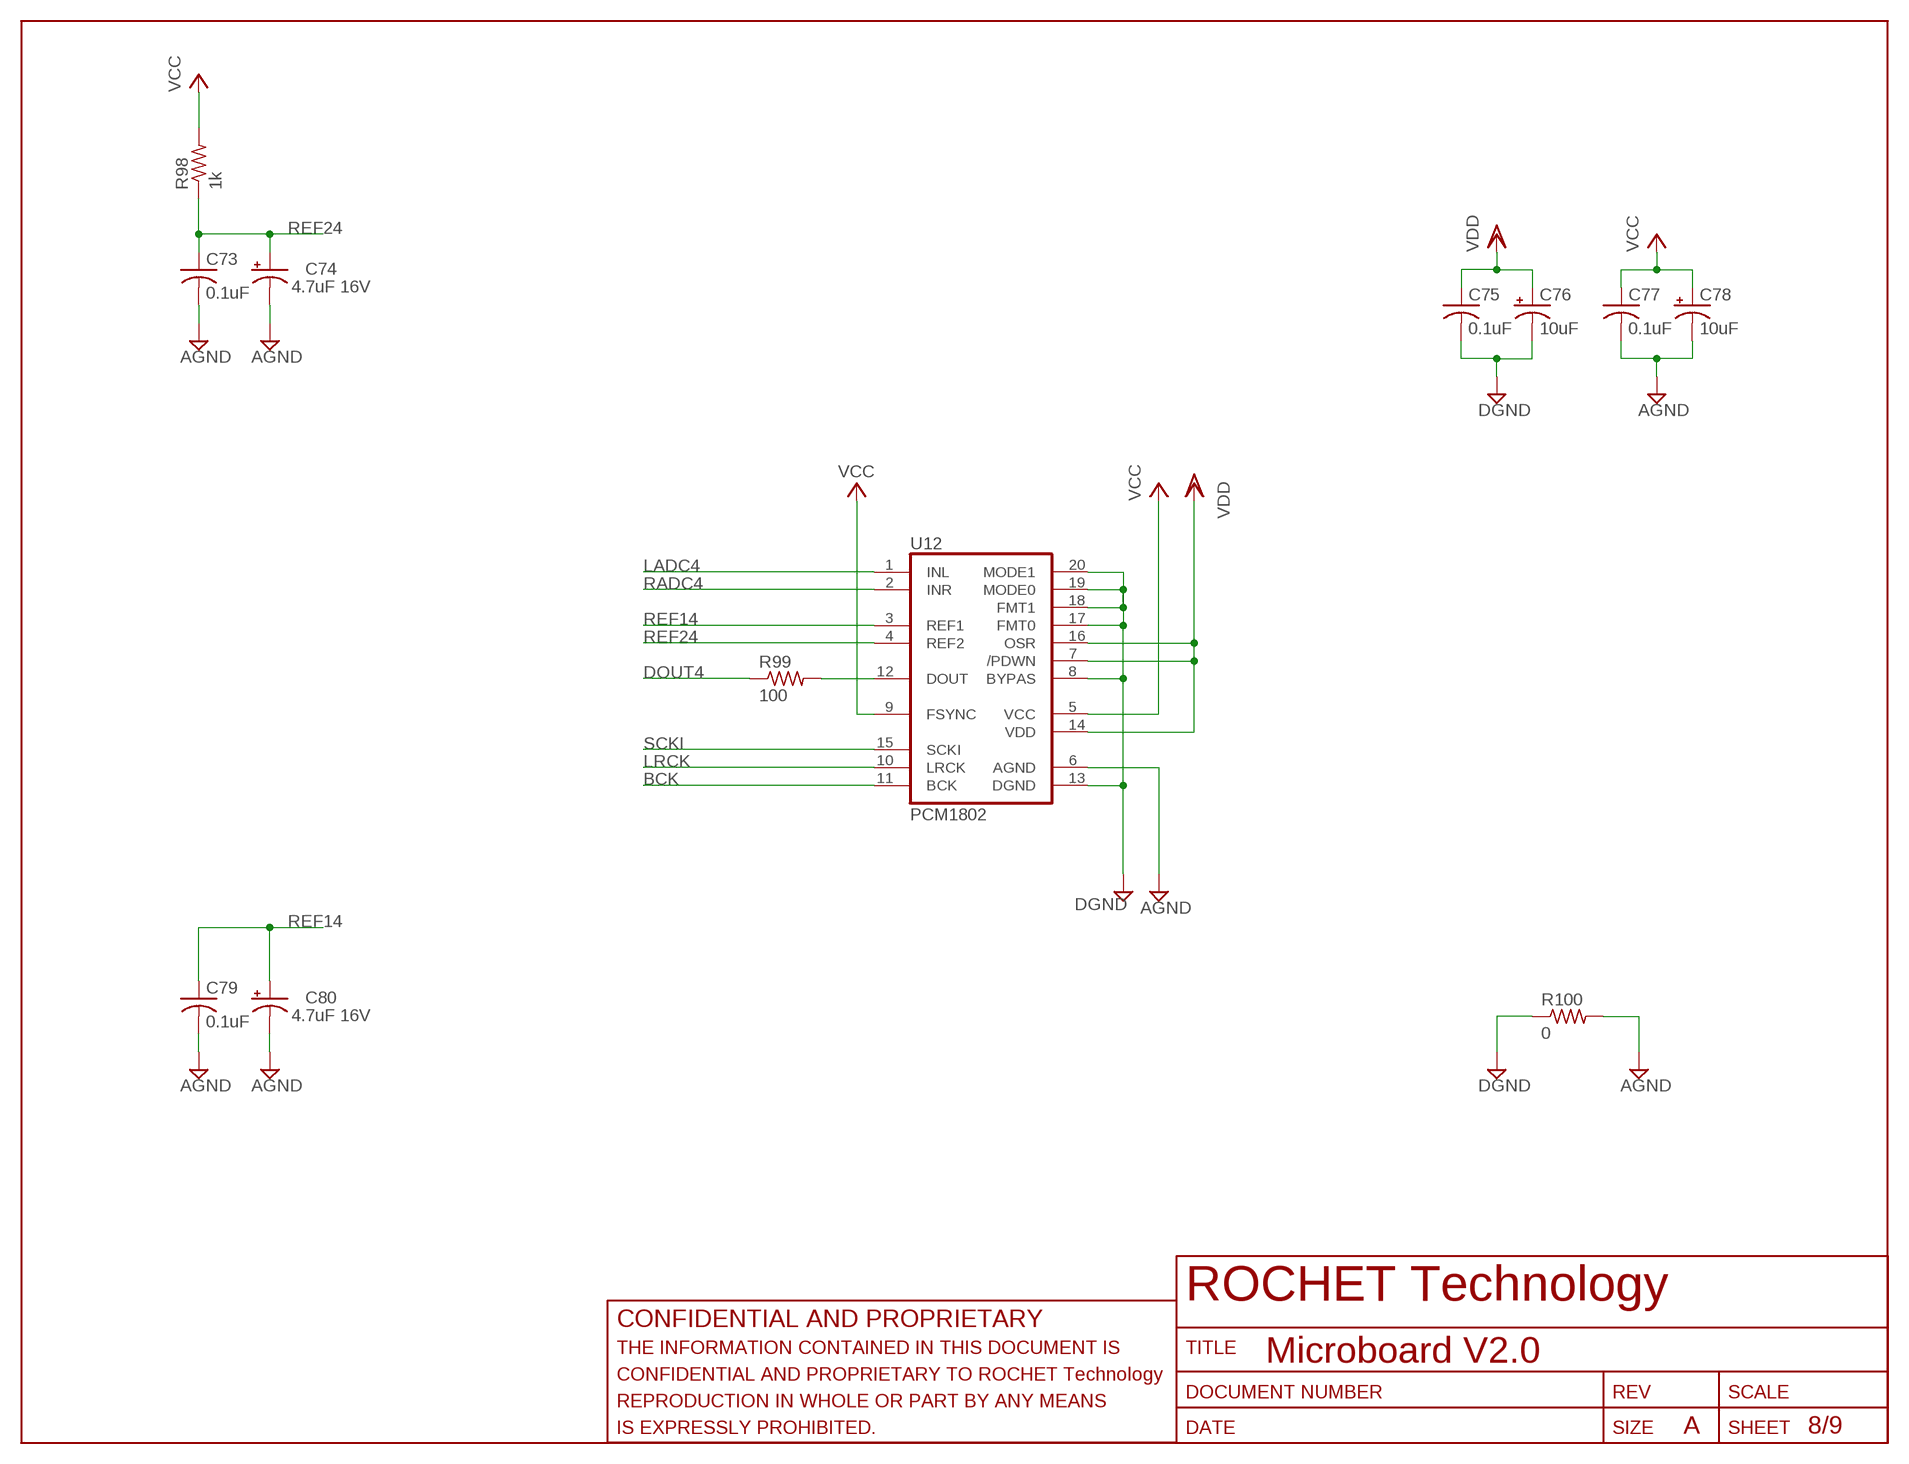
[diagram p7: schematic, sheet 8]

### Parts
C73  0.1uF  C-USC0603  [C0603]
C74  4.7uF 16V  CPOL-USA/3216-18W  [A/3216-18W]
C75  0.1uF  C-USC0603  [C0603]
C76  10uF  CPOL-USA/3216-18W  [A/3216-18W]
C77  0.1uF  C-USC0603  [C0603]
C78  10uF  CPOL-USA/3216-18W  [A/3216-18W]
C79  0.1uF  C-USC0603  [C0603]
C80  4.7uF 16V  CPOL-USA/3216-18W  [A/3216-18W]
R98  1k  R-US_R0805  [R0805]
R99  100  R-US_R0805  [R0805]
R100  0  R-US_R0805  [R0805]
U12  PCM1802  [SSOP20BU]

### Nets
AGND: C73.2 C74.- C77.2 C78.- C79.2 C80.- R100.2 U12.6(AGND) ; also sheet 1,2,3,4,5,6,7,9
BCK: U12.11(BCK) ; also sheet 2,4,6,9
DGND: C75.2 C76.- R100.1 U12.8(BYPAS) U12.13(DGND) U12.17(FMT0) U12.18(FMT1) U12.19(MODE0) U12.20(MODE1) ; also sheet 2,4,6,9
DOUT4: R99.1 ; also sheet 9
LADC4: U12.1(INL) ; also sheet 7
LRCK: U12.10(LRCK) ; also sheet 2,4,6,9
N$35: R99.2 U12.12(DOUT)
RADC4: U12.2(INR) ; also sheet 7
REF14: C79.1 C80.+ U12.3(REF1)
REF24: C73.1 C74.+ R98.1 U12.4(REF2)
SCKI: U12.15(SCKI) ; also sheet 2,4,6,9
VCC: C77.1 C78.+ R98.2 U12.5(VCC) U12.9(FSYNC) ; also sheet 1,2,3,4,5,6,7,9
VDD: C75.1 C76.+ U12.7(/PDWN) U12.14(VDD) U12.16(OSR) ; also sheet 2,4,6,9

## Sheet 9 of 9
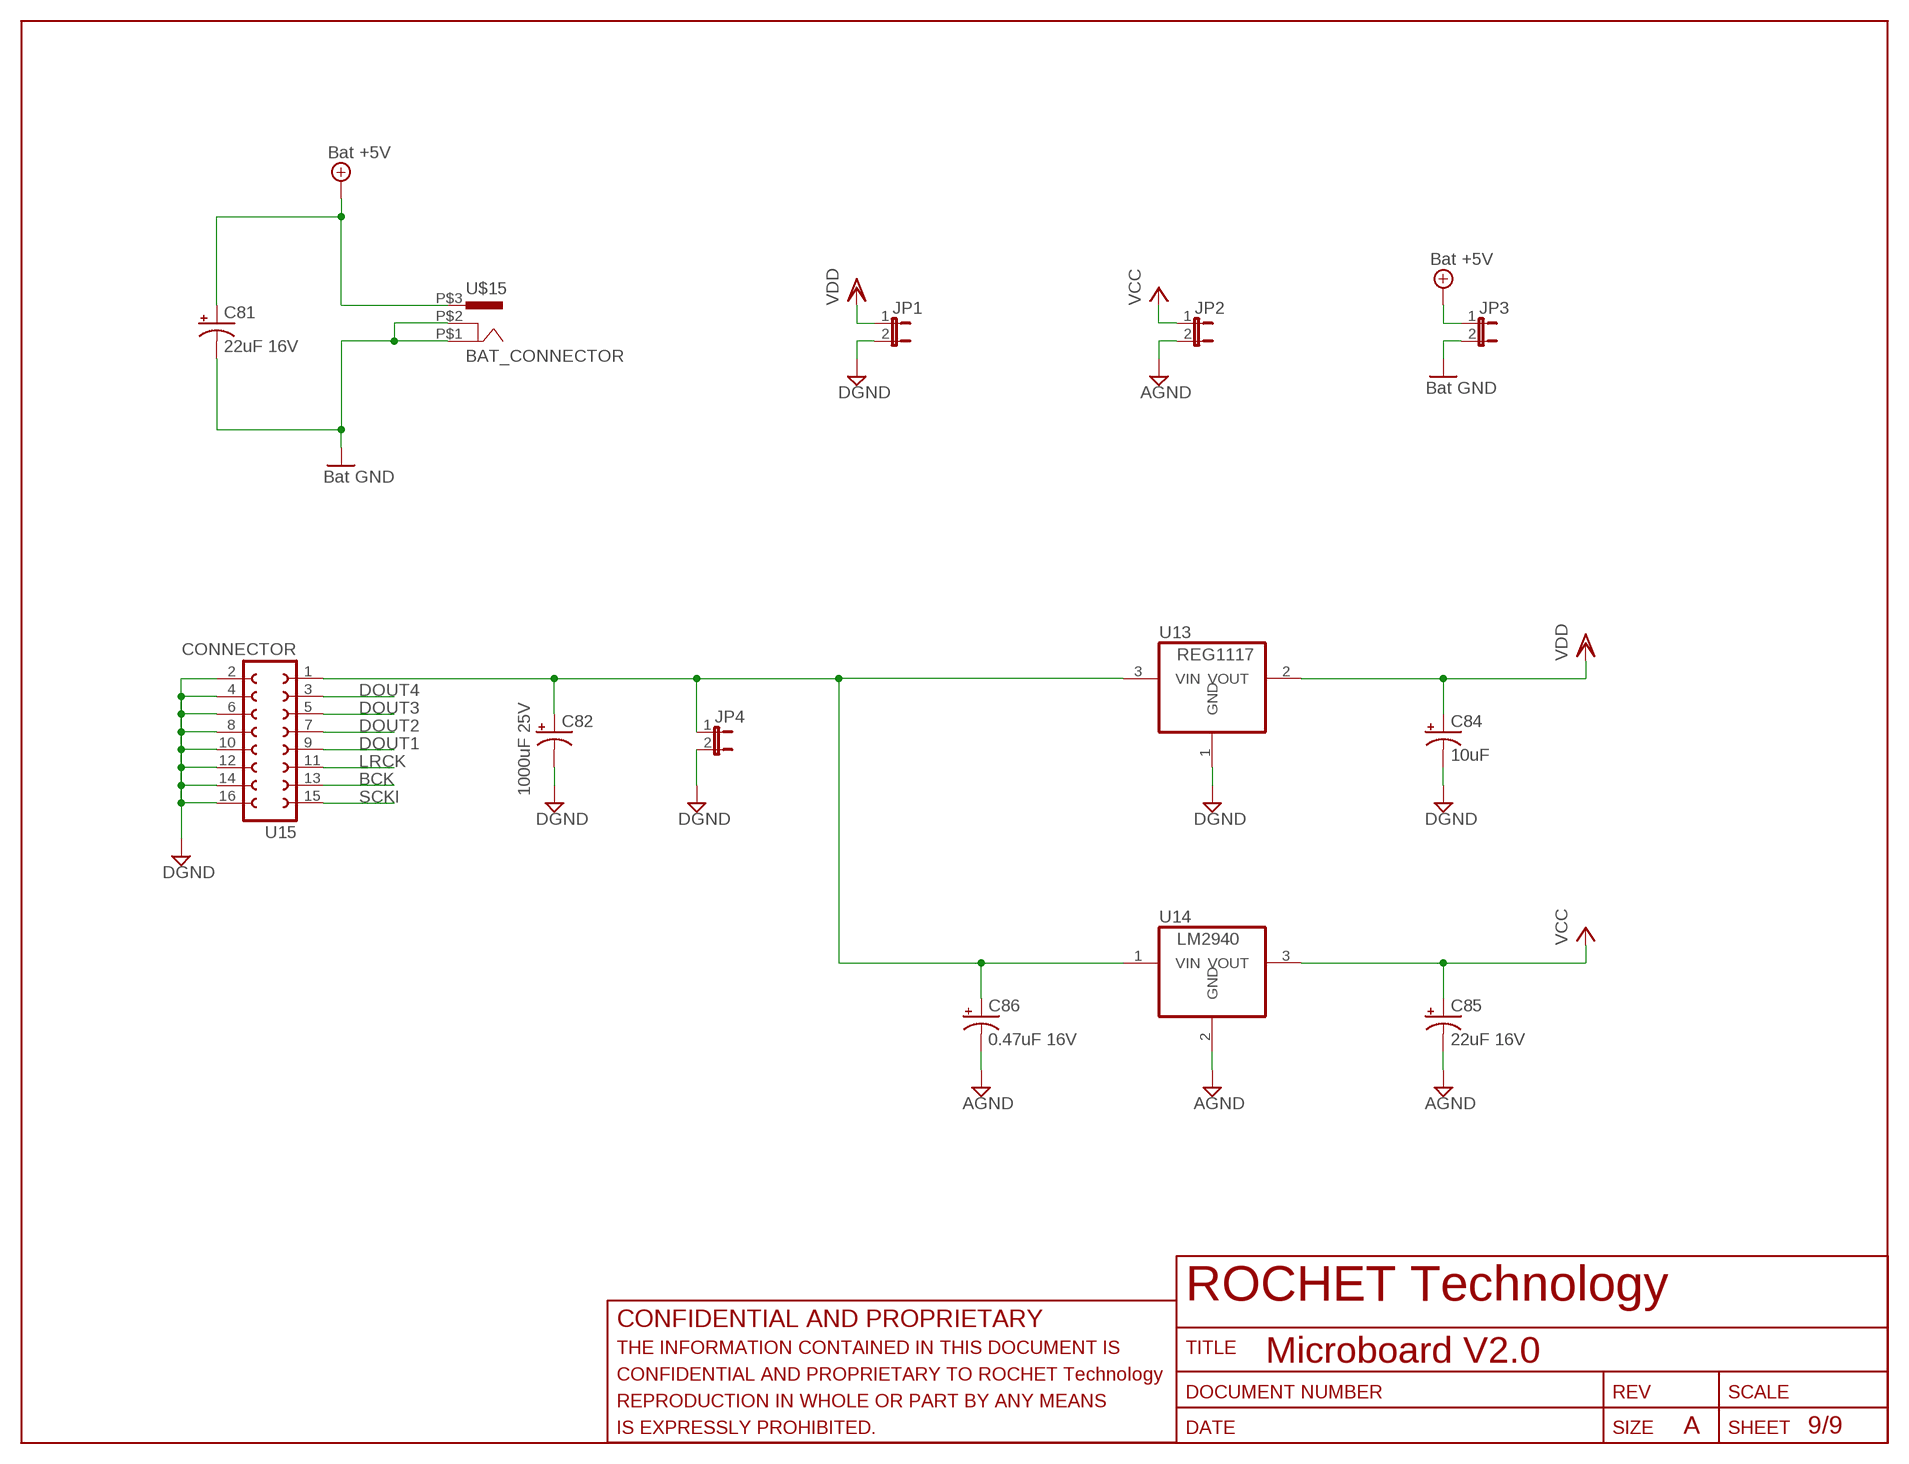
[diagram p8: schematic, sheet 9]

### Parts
C81  22uF 16V  CPOL-USD/7343-31W  [D/7343-31W]
C82  1000uF 25V  CPOL-USE5-10.5  [E5-10,5]
C84  10uF  CPOL-USA/3216-18W  [A/3216-18W]
C85  22uF 16V  CPOL-USD/7343-31W  [D/7343-31W]
C86  0.47uF 16V  CPOL-USA/3216-18W  [A/3216-18W]
JP1  JP1E  [JP1]
JP2  JP1E  [JP1]
JP3  JP1E  [JP1]
JP4  JP1E  [JP1]
U13  REG1117  [SOT223]
U14  LM2940  [SOT223]
U15  CONNECTOR  [FE08-2]
U$15  BAT_CONNECTOR  [PJ-022]

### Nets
+5V: C81.+ JP3.1 U$15.P$3 ; supply symbol labelled Bat +5V ; also sheet 1,3,5,7
AGND: C85.- C86.- JP2.2 U14.2(GND) ; also sheet 1,2,3,4,5,6,7,8
BCK: U15.13 ; also sheet 2,4,6,8
DGND: C82.- C84.- JP1.2 JP4.2 U13.1(GND) U15.2 U15.4 U15.6 U15.8 U15.10 U15.12 U15.14 U15.16 ; also sheet 2,4,6,8
DOUT1: U15.9 ; also sheet 2
DOUT2: U15.7 ; also sheet 4
DOUT3: U15.5 ; also sheet 6
DOUT4: U15.3 ; also sheet 8
GND: C81.- JP3.2 U$15.P$1 U$15.P$2 ; supply symbol labelled Bat GND ; also sheet 1,3,5,7
LRCK: U15.11 ; also sheet 2,4,6,8
N$76: C82.+ C86.+ JP4.1 U13.3(VIN) U14.1(VIN) U15.1
SCKI: U15.15 ; also sheet 2,4,6,8
VCC: C85.+ JP2.1 U14.3(VOUT) ; also sheet 1,2,3,4,5,6,7,8
VDD: C84.+ JP1.1 U13.2(VOUT) ; also sheet 2,4,6,8

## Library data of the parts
C1 C3-C5 C7 C9-C11 C13 C15 C17 C19 C22-C25 C27-C30 C33 C35 C37 C39 C42-C45 C47-C50 C53 C55 C57 C59 C62-C65 C67-C70 C73 C75 C77 C79 = rcl:C-US: CAPACITOR, American symbol
C2 C6 C8 C12 C14 C16 C18 C20 C21 C26 C31 C32 C34 C36 C38 C40 C41 C46 C51 C52 C54 C56 C58 C60 C61 C66 C71 C72 C74 C76 C78 C80-C82 C84-C86 = rcl:CPOL-US: POLARIZED CAPACITOR, American symbol
JP1-JP4 = jumper:JP1E: JUMPER
MIC1-MIC8 = con-amp:MTA02-100: AMP connector
POT1-POT8 = microboard:P7J471CT-ND
R1-R8 R10-R18 R20-R35 R37-R46 R48-R60 R62-R71 R73-R85 R87-R96 R98-R100 = rcl:R-US_: RESISTOR, American symbol
U1 U2 U4 U5 U7 U8 U10 U11 = microboard:OPA2228: High Precision, Low Noise OPERATIONAL AMPLIFIERS
U3 U6 U9 U12 = my_library:PCM1802: 24 bits ADC PCM1802
U13 = my_library:REG1117
U14 = my_library:LM2940: LDO regulator
U15 = microboard:CONNECTOR: 8*2
U$15 = microboard:BAT_CONNECTOR

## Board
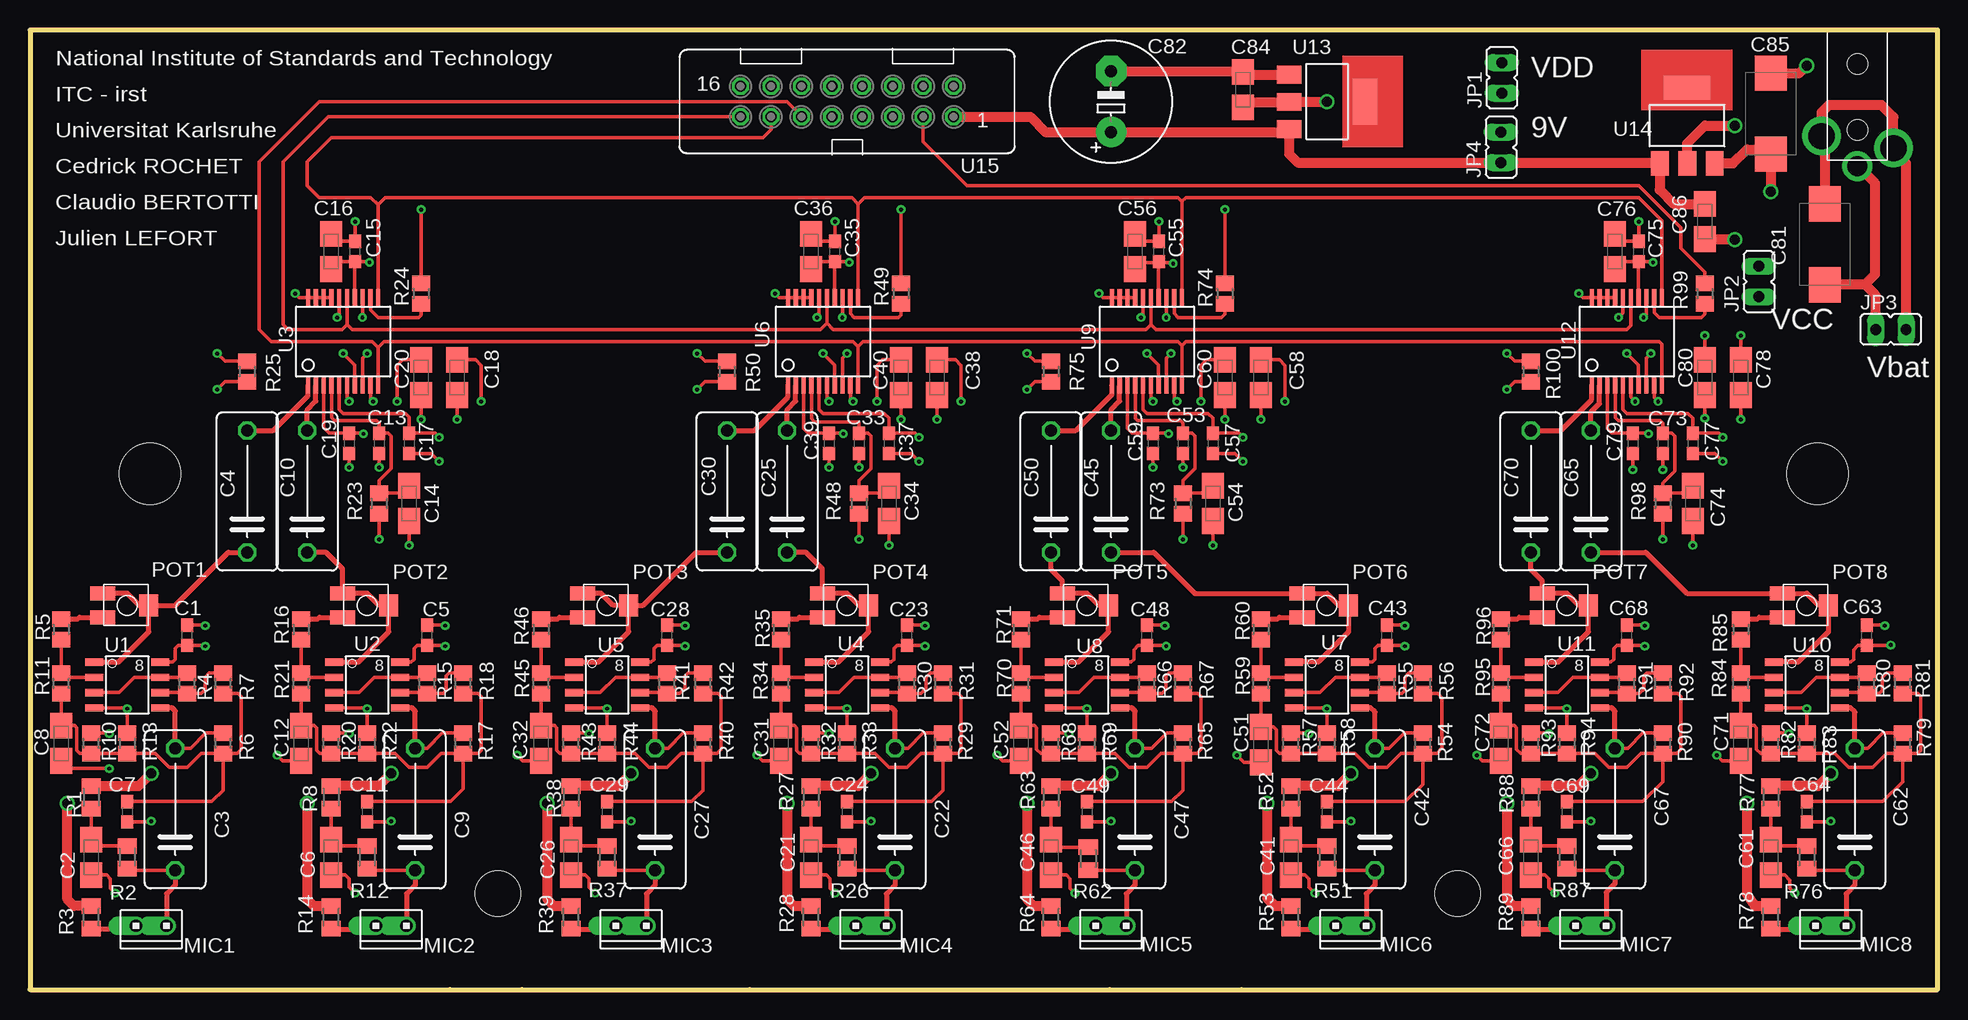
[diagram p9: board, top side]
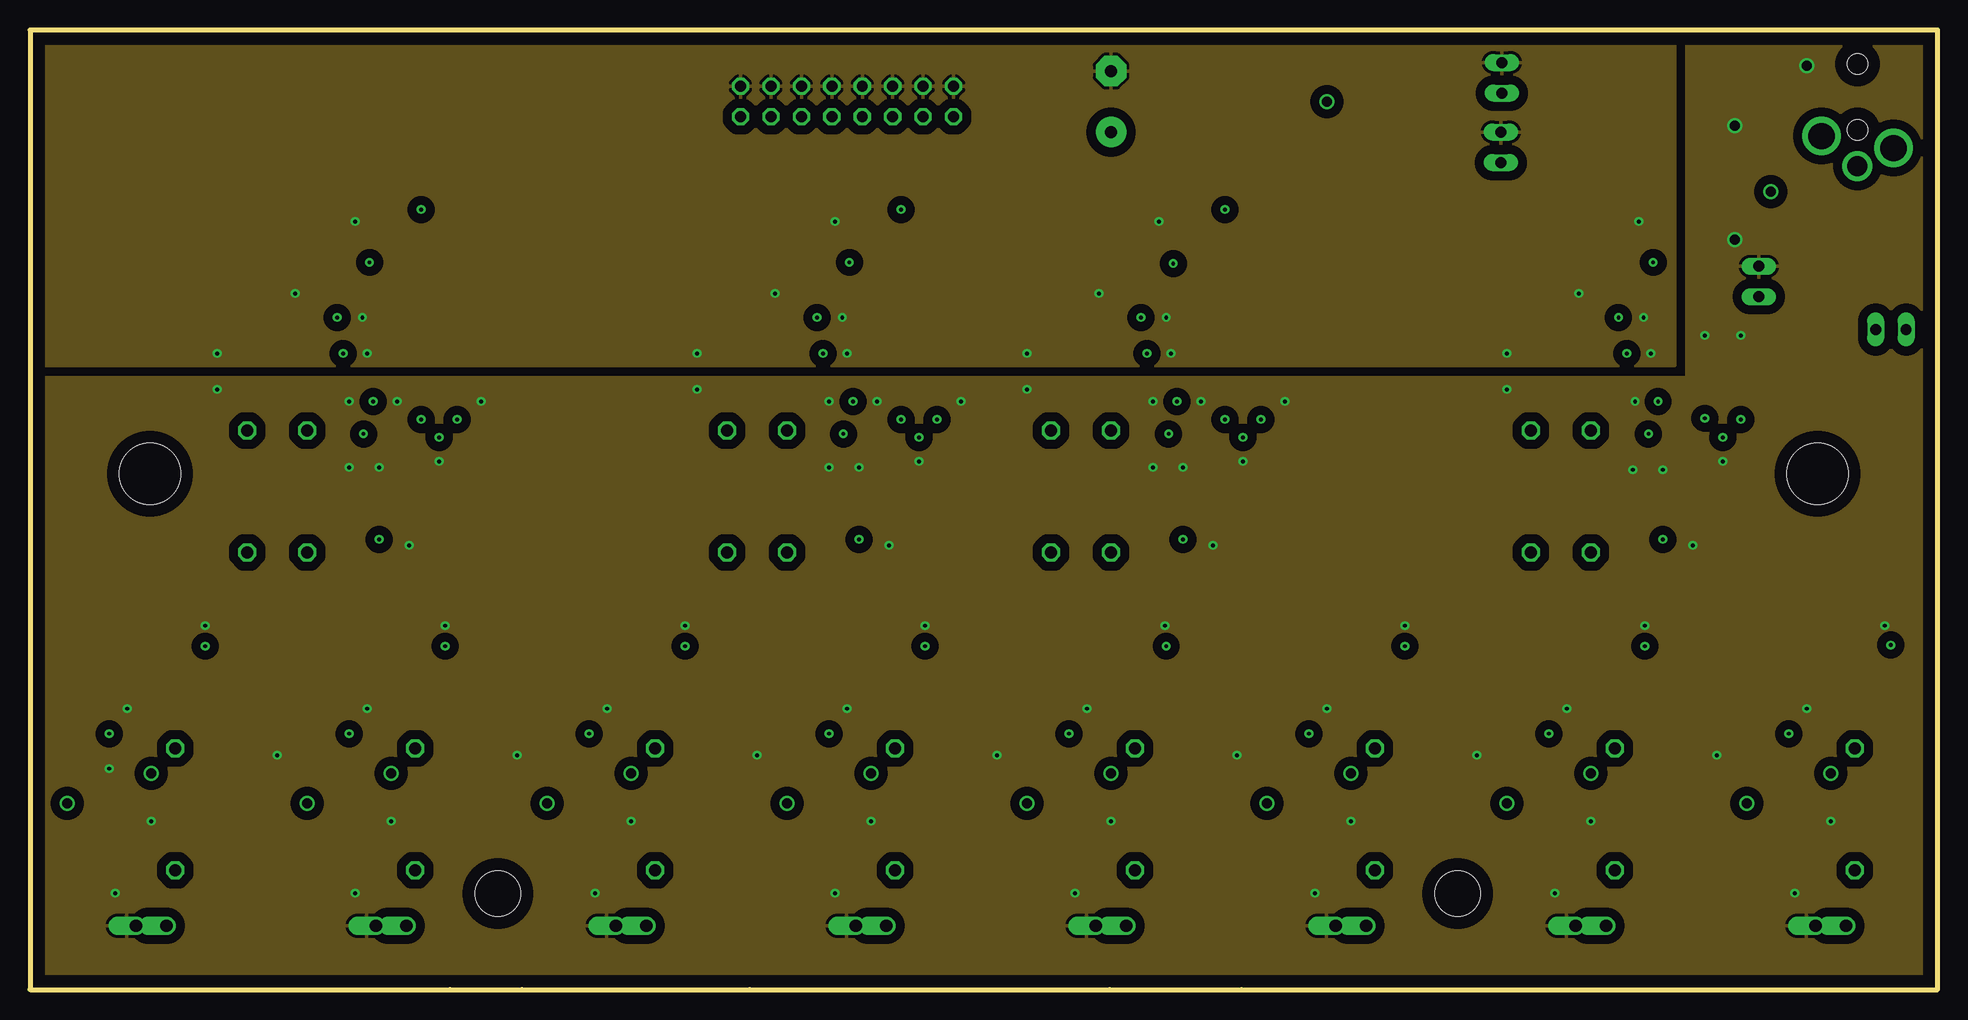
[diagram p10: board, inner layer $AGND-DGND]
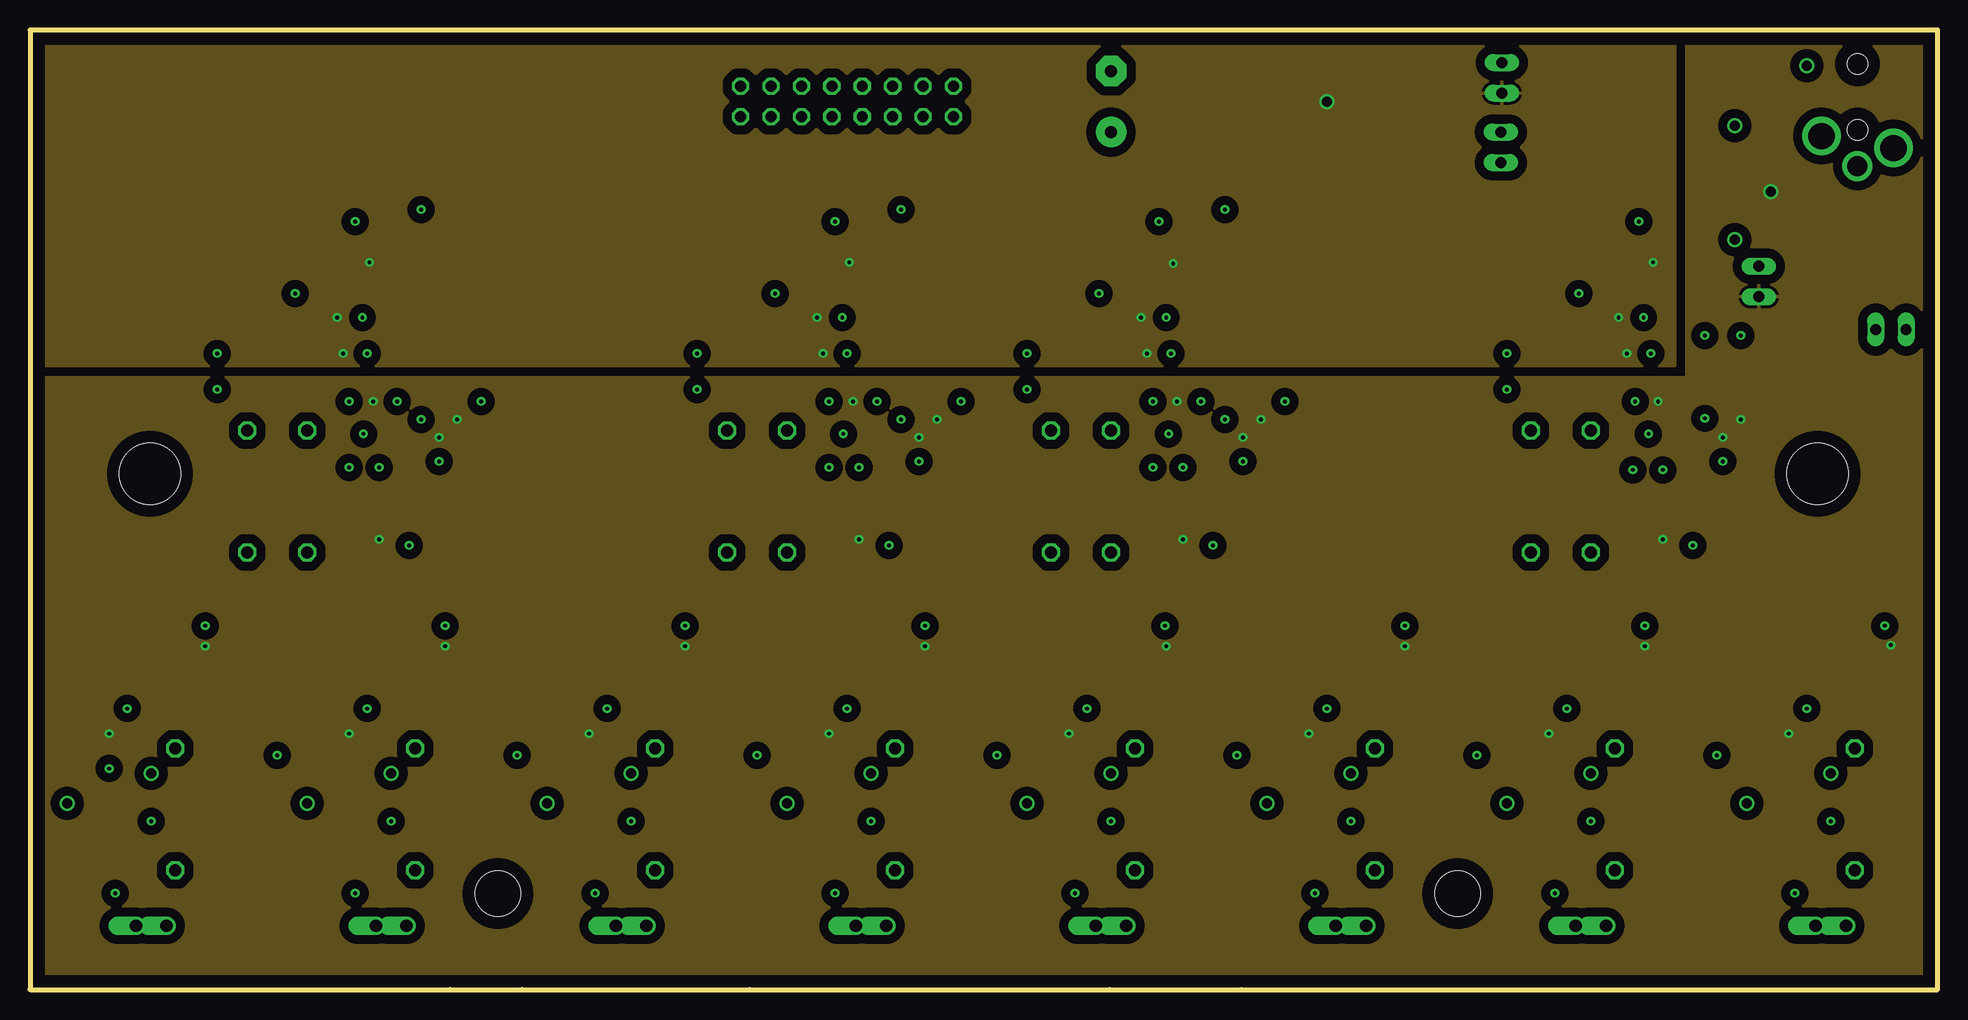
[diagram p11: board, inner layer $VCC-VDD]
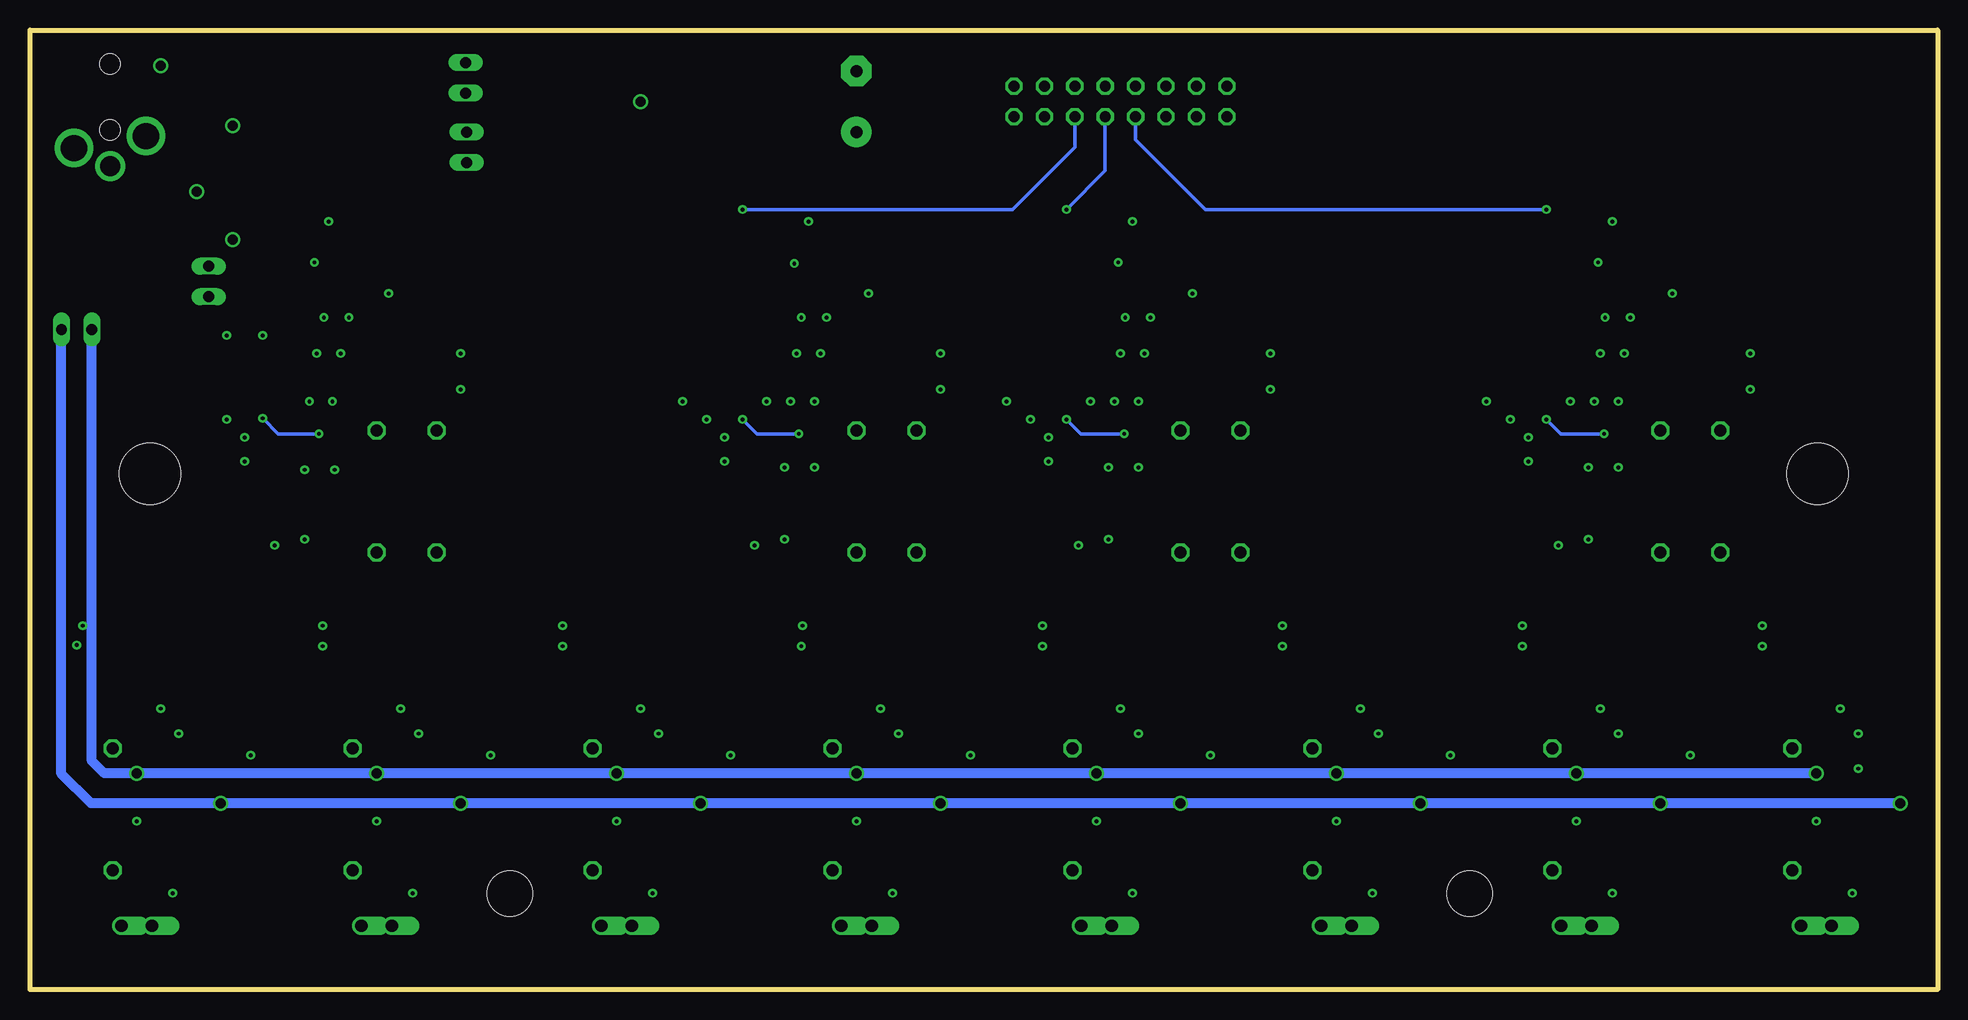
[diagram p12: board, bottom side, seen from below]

Size 159 x 80 mm. Coordinates in mm from the lower left corner, seen from the top.
Outline: 35,0 159,0 159,80 0,80 0,0 35,0
Outline: 35,0 90,0
Outline: 35,0 60,0
Outline: 41,0 101,0
Copper layers used: Top, $AGND-DGND, $VCC-VDD, Bottom
Holes 5.08 mm at 10,43 149,43
Holes 3.81 mm at 39,8 119,8
tKeepout: area 115.6,4.6 to 122.4,11.4; area 35.6,4.6 to 42.4,11.4; area 5.9,38.9 to 14.1,47.1; area 144.9,38.9 to 153.1,47.1

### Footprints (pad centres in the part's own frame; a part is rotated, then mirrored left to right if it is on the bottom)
C0603 = smd 1.1 x 1: 1 -0.85,0; 2 0.85,0
A/3216-18W = smd 2.15 x 1.8: + 1.475,0; - -1.475,0
C102-054X133 = drill 1.016 octagon: 1 -5.08,0; 2 5.08,0
D/7343-31W = smd 2.95 x 2.7: + 3.375,0; - -3.375,0
E5-10,5 = drill 1.016 pad 2.54 round: + -2.54,0 | drill 1.016 pad 2.54 octagon: - 2.54,0
JP1 = drill 0.914 long: 1 0,-1.27; 2 0,1.27
10X02MTA = drill 1.016 offset: 1 1.27,0; 2 -1.27,0
POT_EVM7J = smd 1.2 x 2.1: P$1 -1,-2.05; P$3 1,-2.05 | smd 1.8 x 1.6: P$2 0,1.8
M0805 = smd 1.3 x 1.6: 1 -0.95,0; 2 0.95,0
R0805 = smd 1.3 x 1.5: 1 -0.85,0; 2 0.85,0
SO-08 = smd 1.524 x 0.61: 1 -2.743,1.27; 2 -2.743,0; 3 -2.743,-1.27; 4 -2.743,-2.54; 5 2.743,-2.54; 6 2.743,-1.27; 7 2.743,0; 8 2.743,1.27
SSOP20BU = smd 0.348 x 1.397: 1 -2.925,-3.656; 2 -2.275,-3.656; 3 -1.625,-3.656; 4 -0.975,-3.656; 5 -0.325,-3.656; 6 0.325,-3.656; 7 0.975,-3.656; 8 1.625,-3.656; 9 2.275,-3.656; 10 2.925,-3.656; 11 2.925,3.656; 12 2.275,3.656; 13 1.625,3.656; 14 0.975,3.656; 15 0.325,3.656; 16 -0.325,3.656; 17 -0.975,3.656; 18 -1.625,3.656; 19 -2.275,3.656; 20 -2.925,3.656
SOT223 = smd 1.499 x 2.007: 1 -2.261,-3.15; 2 0.025,-3.15; 3 2.311,-3.15 | smd 3.81 x 2.007: 4 0,3.15
FE08-2 = drill 0.914 octagon: 1 -8.89,1.27; 2 -8.89,-1.27; 3 -6.35,1.27; 4 -6.35,-1.27; 5 -3.81,1.27; 6 -3.81,-1.27; 7 -1.27,1.27; 8 -1.27,-1.27; 9 1.27,1.27; 10 1.27,-1.27; 11 3.81,1.27; 12 3.81,-1.27; 13 6.35,1.27; 14 6.35,-1.27; 15 8.89,1.27; 16 8.89,-1.27
PJ-022 = drill 2.184 round: P$1 3.92,-3.04; P$2 4.92,2.96 | drill 1.676 round: P$3 6.42,-0.04 | hole 1.676: -2.08,-0.04; 3.42,-0.04

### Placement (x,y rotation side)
C1  13.11,29.52 90 top
C2  5.11,11.03 90 top
C3  12.11,15.03 90 top
C4  18.11,41.52 90 top
C5  33.11,29.52 90 top
C6  25.11,11.03 90 top
C7  8.11,14.83 270 top
C8  2.61,20.52 90 top
C9  32.11,15.03 90 top
C10  23.11,41.52 90 top
C11  28.11,14.83 270 top
C12  22.61,20.52 90 top
C13  29.11,45.52 270 top
C14  31.61,40.52 90 top
C15  27.11,61.52 90 top
C16  25.11,61.52 270 top
C17  31.61,45.52 270 top
C18  35.61,51.02 270 top
C19  26.61,45.52 270 top
C20  32.61,51.02 270 top
C21  65.11,11.03 90 top
C22  72.11,15.03 90 top
C23  73.11,29.52 90 top
C24  68.11,14.83 270 top
C25  63.11,41.52 90 top
C26  45.11,11.03 90 top
C27  52.11,15.03 90 top
C28  53.11,29.52 90 top
C29  48.11,14.83 270 top
C30  58.11,41.52 90 top
C31  62.61,20.52 90 top
C32  42.61,20.52 90 top
C33  69.11,45.52 270 top
C34  71.61,40.52 90 top
C35  67.11,61.52 90 top
C36  65.11,61.52 270 top
C37  71.61,45.52 270 top
C38  75.61,51.02 270 top
C39  66.61,45.52 270 top
C40  72.61,51.02 270 top
C41  105.11,11.03 90 top
C42  112.11,15.03 90 top
C43  113.11,29.52 90 top
C44  108.11,14.83 270 top
C45  90.11,41.52 90 top
C46  85.11,11.03 90 top
C47  92.11,15.03 90 top
C48  93.11,29.52 90 top
C49  88.11,14.83 270 top
C50  85.11,41.52 90 top
C51  102.61,20.42 90 top
C52  82.61,20.52 90 top
C53  96.11,45.52 270 top
C54  98.61,40.52 90 top
C55  94.11,61.52 90 top
C56  92.11,61.52 270 top
C57  98.61,45.52 270 top
C58  102.61,51.02 270 top
C59  93.61,45.52 270 top
C60  99.61,51.02 270 top
C61  145.11,11.03 90 top
C62  152.11,15.03 90 top
C63  153.11,29.52 90 top
C64  148.11,14.83 270 top
C65  130.11,41.52 90 top
C66  125.11,11.03 90 top
C67  132.11,15.03 90 top
C68  133.11,29.52 90 top
C69  128.11,14.83 270 top
C70  125.11,41.52 90 top
C71  142.61,20.52 90 top
C72  122.61,20.52 90 top
C73  136.11,45.52 270 top
C74  138.61,40.52 90 top
C75  134.11,61.52 90 top
C76  132.11,61.52 270 top
C77  138.61,45.52 270 top
C78  142.61,51.02 270 top
C79  133.61,45.52 270 top
C80  139.61,51.02 270 top
C81  149.61,62.12 270 top
C82  90.11,74.03 90 top
C84  101.11,75.03 270 top
C85  145.11,73.03 270 top
C86  139.61,64.03 90 top
JP1  122.69,76.02 0 top
JP2  144.11,59.02 0 top
JP3  155.11,55.02 270 top
JP4  122.61,70.23 0 top
MIC1  10.11,5.33 180 top
MIC2  30.11,5.33 180 top
MIC3  50.11,5.33 180 top
MIC4  70.11,5.33 180 top
MIC5  90.11,5.33 180 top
MIC6  110.11,5.33 180 top
MIC7  130.11,5.33 180 top
MIC8  150.11,5.33 180 top
POT1  8.1,32.02 270 top
POT2  28.1,32.02 270 top
POT3  48.1,32.02 270 top
POT4  68.1,32.02 270 top
POT5  88.1,32.02 270 top
POT6  108.1,32.02 270 top
POT7  128.11,32.02 270 top
POT8  148.1,32.02 270 top
R1  5.11,16.02 90 top
R2  8.11,11.03 90 top
R3  5.11,6.03 270 top
R4  13.11,25.52 90 top
R5  2.61,30.02 270 top
R6  16.11,20.52 90 top
R7  16.11,25.52 90 top
R8  25.11,16.02 90 top
R10  5.11,20.52 90 top
R11  2.61,25.52 90 top
R12  28.11,11.03 90 top
R13  8.11,20.52 270 top
R14  25.11,6.03 270 top
R15  33.11,25.52 90 top
R16  22.61,30.02 270 top
R17  36.11,20.52 90 top
R18  36.11,25.52 90 top
R20  25.11,20.52 90 top
R21  22.61,25.52 90 top
R22  28.11,20.52 270 top
R23  29.11,40.52 270 top
R24  32.61,58.02 270 top
R25  18.11,51.52 270 top
R26  68.11,11.03 90 top
R27  65.11,16.02 90 top
R28  65.11,6.03 270 top
R29  76.11,20.52 90 top
R30  73.11,25.52 90 top
R31  76.11,25.52 90 top
R32  65.11,20.52 90 top
R33  68.11,20.52 270 top
R34  62.61,25.52 90 top
R35  62.61,30.02 270 top
R37  48.11,11.03 90 top
R38  45.11,16.02 90 top
R39  45.11,6.03 270 top
R40  56.11,20.52 90 top
R41  53.11,25.52 90 top
R42  56.11,25.52 90 top
R43  45.11,20.52 90 top
R44  48.11,20.52 270 top
R45  42.61,25.52 90 top
R46  42.61,30.02 270 top
R48  69.11,40.52 270 top
R49  72.61,58.02 270 top
R50  58.11,51.52 270 top
R51  108.11,11.03 90 top
R52  105.11,16.02 90 top
R53  105.11,6.03 270 top
R54  116.11,20.52 90 top
R55  113.11,25.52 90 top
R56  116.11,25.52 90 top
R57  105.11,20.52 90 top
R58  108.11,20.52 270 top
R59  102.61,25.52 90 top
R60  102.61,30.02 270 top
R62  88.21,10.93 90 top
R63  85.11,16.02 90 top
R64  85.11,6.03 270 top
R65  96.11,20.52 90 top
R66  93.11,25.52 90 top
R67  96.11,25.52 90 top
R68  85.11,20.52 90 top
R69  88.11,20.52 270 top
R70  82.61,25.52 90 top
R71  82.61,30.02 270 top
R73  96.11,40.52 270 top
R74  99.61,58.02 270 top
R75  85.11,51.52 270 top
R76  148.11,11.03 90 top
R77  145.11,16.02 90 top
R78  145.11,6.03 270 top
R79  156.11,20.52 90 top
R80  153.11,25.52 90 top
R81  156.11,25.52 90 top
R82  145.11,20.52 90 top
R83  148.11,20.52 270 top
R84  142.61,25.52 90 top
R85  142.61,30.02 270 top
R87  128.11,11.03 90 top
R88  125.11,16.02 90 top
R89  125.11,6.03 270 top
R90  136.11,20.52 90 top
R91  133.11,25.52 90 top
R92  136.11,25.52 90 top
R93  125.11,20.52 90 top
R94  128.11,20.52 270 top
R95  122.61,25.52 90 top
R96  122.61,30.02 270 top
R98  136.11,40.52 270 top
R99  139.61,58.02 270 top
R100  125.11,51.52 270 top
U1  8.11,26.02 0 top
U2  28.11,26.02 0 top
U3  26.11,54.02 0 top
U4  68.11,26.02 0 top
U5  48.11,26.02 0 top
U6  66.11,54.02 0 top
U7  108.11,26.02 0 top
U8  88.11,26.02 0 top
U9  93.11,54.02 0 top
U10  148.11,26.02 0 top
U11  128.11,26.02 0 top
U12  133.11,54.02 0 top
U13  108.11,74.03 270 top
U14  138.11,72.03 0 top
U15  68.11,74.03 180 top
U$15  152.37,75.08 270 top

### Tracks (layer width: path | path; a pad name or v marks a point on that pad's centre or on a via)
+5V  (via drill 0.81)
  Top 0.813: R88.2 129.06,16.97 v130.11,18.02 | R52.2 109.06,16.97 v110.11,18.02 | R63.2 89.06,16.97 v90.11,18.02 | R27.2 69.06,16.97 v70.11,18.02 | R77.2 149.06,16.97 v150.11,18.02 | R38.2 49.06,16.97 v50.11,18.02 | R8.2 29.06,16.97 v30.11,18.02 | R1.2 9.06,16.97 v10.11,18.02 | 152.98,58.75 C81.+ | JP3.1 153.84,57.89 152.98,58.75 | 152.98,58.75 152.98,58.8 153.81,59.62 153.81,67.23 152.38,68.66 U$15.P$3
  Bottom 0.813: JP3.1 153.84,19.05 152.81,18.02 v150.11,18.02 v130.11,18.02 v110.11,18.02 v90.11,18.02 v70.11,18.02 v50.11,18.02 v30.11,18.02 v10.11,18.02
AGND  (via drill 0.3, 0.81)
  Top 0.305: C61.- 146.28,9.55 146.71,9.12 146.71,8.43 v147.11,8.03 | C63.2 154.66,30.38 v154.61,30.32 | C64.2 150.06,13.97 v150.11,14.03 | C69.2 130.06,13.97 v130.11,14.03 | C66.- 126.28,9.55 126.61,9.22 126.61,8.53 v127.11,8.03 | C68.2 134.66,30.38 v134.61,30.32 | C41.- 106.28,9.55 106.61,9.22 106.61,8.53 v107.11,8.03 | C44.2 110.06,13.97 v110.11,14.03 | C43.2 114.66,30.38 v114.61,30.32 | C46.- 86.38,9.55 86.71,9.22 86.71,8.43 v87.11,8.03 | C49.2 90.06,13.97 v90.11,14.03 | C48.2 94.66,30.38 v94.61,30.32 | C21.- 66.38,9.55 66.71,9.22 66.71,8.43 v67.11,8.03 | C24.2 70.06,13.97 v70.11,14.03 | C23.2 74.66,30.38 v74.61,30.32 | C26.- 46.28,9.55 46.61,9.22 46.61,8.53 v47.11,8.03 | C29.2 50.06,13.97 v50.11,14.03 | C28.2 54.66,30.38 v54.61,30.32 | C6.- 26.28,9.55 26.61,9.22 26.61,8.53 v27.11,8.03 | C11.2 30.06,13.97 v30.11,14.03 | C5.2 34.66,30.38 v34.61,30.32 | C2.- 6.38,9.55 6.71,9.22 6.71,8.43 v7.11,8.03 | C7.2 10.06,13.97 v10.11,14.03 | C1.2 14.66,30.38 v14.61,30.32 | C78.- v142.61,54.52 | C80.- v139.61,54.52 | R100.2 123.76,50.67 v123.11,50.02 | C79.2 v133.61,43.32 | C73.2 v136.11,43.32 | v138.61,37.02 C74.- | v98.61,37.02 C54.- | C59.2 v93.61,43.52 | C53.2 v96.11,43.52 | U9.6 93.43,49.2 v93.61,49.02 | U12.6 133.43,49.4 v133.81,49.02 | R75.2 83.76,50.67 v83.11,50.02 | C58.- 104.13,52.5 104.61,52.02 v104.61,49.02 | C60.- 98.08,52.5 97.61,52.02 v97.61,49.02 | v71.61,37.02 C34.- | C77.2 140.46,44.67 v141.11,44.02 | C57.2 100.46,44.67 v101.11,44.02 | C38.- 77.13,52.5 77.61,52.02 v77.61,49.02 | C40.- 71.08,52.5 70.61,52.02 v70.61,49.02 | U6.6 66.43,49.2 v66.61,49.02 | R50.2 56.26,50.67 v55.61,50.02 | C20.- 31.08,52.5 30.61,52.02 v30.61,49.02
  Top 0.305: C18.- 37.13,52.5 37.61,52.02 v37.61,49.02 | U3.6 26.43,49.2 v26.61,49.02 | C37.2 73.46,44.67 v74.11,44.02 | C33.2 v69.11,43.52 | C39.2 v66.61,43.52 | C17.2 33.46,44.67 v34.11,44.02 | v31.61,37.02 C14.- | C13.2 v29.11,43.52 | C19.2 v26.61,43.52 | R25.2 16.26,50.67 v15.61,50.02 | C71.- 141.08,19.05 v140.61,19.52 | C72.- 121.08,19.05 v120.61,19.52 | C51.- 101.18,18.95 v100.61,19.52 | C52.- 81.08,19.05 v80.61,19.52 | C31.- 61.08,19.05 v60.61,19.52 | C32.- 41.08,19.05 v40.61,19.52 | C12.- 21.08,19.05 v20.61,19.52 | U1.4 8.05,23.48 v8.11,23.42 R13.1 | U2.4 28.05,23.48 v28.11,23.42 R22.1 | U5.4 48.05,23.48 v48.11,23.42 R44.1 | U4.4 68.05,23.48 v68.11,23.42 R33.1 | U8.4 88.05,23.48 v88.11,23.42 R69.1 | U7.4 108.05,23.48 v108.11,23.42 R58.1 | U11.4 128.05,23.48 v128.11,23.42 R94.1 | U10.4 148.05,23.48 v148.11,23.42 R83.1 | C8.- 2.61,19.12 3.31,18.42 v6.61,18.42
  Top 0.406: MIC1.1 6.91,5.33 6.66,5.08 R3.2 | MIC2.1 27.41,5.33 27.11,5.03 25.11,5.03 R14.2 | MIC3.1 47.41,5.33 47.11,5.03 45.11,5.03 R39.2 | MIC4.1 67.41,5.33 67.11,5.03 65.11,5.03 R28.2 | MIC5.1 87.41,5.33 87.11,5.03 85.11,5.03 R64.2 | MIC6.1 107.41,5.33 107.11,5.03 105.11,5.03 R53.2 | MIC7.1 127.41,5.33 127.11,5.03 125.11,5.03 R89.2 | MIC8.1 147.41,5.33 147.11,5.03 145.11,5.03 R78.2
  Top 0.813: C85.- 147.48,76.4 v148.11,77.03 | U14.2 138.13,70.55 139.61,72.03 v142.11,72.03 | C86.- 142.08,62.55 v142.11,62.52
  pour $AGND-DGND (isolate 0.762): 0.61,0.53 158.61,0.53 158.61,79.53 138.11,79.53 138.11,51.02 0.61,51.02
BCK
  Top 0.305: U15.13 61.76,71.68 61.11,71.03 25.11,71.03 23.11,69.03 23.11,67.03 24.11,66.03 28.41,66.03 29.01,65.43 | U3.11 29.03,65.4 29.01,65.43 | 29.01,65.43 29.61,66.03 68.51,66.03 69.03,65.5 | 69.03,65.5 U6.11 | 69.03,65.5 69.56,66.03 95.71,66.03 96.03,65.7 | 96.03,65.7 U9.11 | 96.03,65.7 96.03,65.71 96.35,66.03 134.11,66.03 136.03,64.1 U12.11
DGND  (via drill 0.3)
  Top 0.305: U12.8 134.73,52.65 v135.11,53.02 | U12.13 134.73,56.25 v134.51,56.02 | 130.81,57.68 U12.19 131.46,57.68 131.47,57.67 131.47,57.68 U12.18 U12.17 | U12.17 | U12.17 | 130.81,57.68 130.8,57.68 | R100.1 123.76,52.38 v123.11,53.02 | U9.13 94.73,56.05 v94.71,56.02 | 90.81,57.68 U9.19 U9.18 | 90.81,57.68 90.8,57.68 | U9.18 | U9.17 92.12,57.68 92.11,57.68 U9.18 | v134.11,64.03 C75.2 132.66,62.38 132.11,62.92 C76.- | v94.11,64.03 C55.2 92.76,62.38 92.11,63.02 C56.- | U9.8 94.73,52.65 v95.11,53.02 | R75.1 83.76,52.38 v83.11,53.02 | v67.11,64.03 C35.2 65.76,62.38 65.11,63.02 C36.- | U6.13 67.73,56.05 v67.71,56.02 | U6.18 U6.19 63.82,57.68 63.81,57.68 U6.20 62.45,57.68 v62.11,58.02 | U6.18 | U6.17 65.12,57.68 U6.18 | U3.17 25.11,57.68 U3.18 24.47,57.68 24.46,57.68 U3.19 23.82,57.68 U3.20 22.45,57.68 v22.11,58.02 | C16.- 25.11,63.02 25.76,62.38 C15.2 v27.11,64.03 | U3.13 27.73,56.05 v27.71,56.02 | v129.11,58.02 129.45,57.68 U12.20 130.19,57.68 130.2,57.68 130.81,57.68 | v89.11,58.02 89.45,57.68 U9.20 90.81,57.68 | U6.8 67.73,52.65 v68.11,53.02 | R50.1 56.26,52.38 v55.61,53.02 | U3.8 27.73,52.65 v28.11,53.02 | R25.1 16.26,52.38 v15.61,53.02
  Top 0.61: 101.11,77.03 101.84,76.29 | 101.11,76.57 101.11,77.03 | 101.11,76.03 C84.- 101.11,77.03
  Top 0.813: 101.84,76.29 U13.1 | C82.- 101.11,76.57
  pour $AGND-DGND (isolate 0.762): 0.61,52.02 137.11,52.02 137.11,79.53 0.61,79.53
DOUT1  (via drill 0.3)
  Top 0.305: R24.1 v32.61,65.03
  Bottom 0.305: U15.9 66.84,70.86 61.01,65.03 v32.61,65.03
DOUT2  (via drill 0.3)
  Top 0.305: R49.1 v72.61,65.03
  Bottom 0.305: U15.7 69.38,68.26 v72.61,65.03
DOUT3  (via drill 0.3)
  Top 0.305: v99.61,65.03 R74.1
  Bottom 0.305: U15.5 71.92,70.22 77.11,65.03 v99.61,65.03
DOUT4
  Top 0.305: R99.1 139.61,59.82 137.61,61.82 137.61,63.52 134.11,67.03 78.11,67.03 74.46,70.68 U15.3
GND  (via drill 0.81)
  Top 0.813: R78.1 143.76,6.98 143.11,7.93 v143.11,15.53 | R89.1 123.66,6.98 123.11,7.53 v123.11,15.53 | R28.1 63.66,6.98 63.11,7.53 v63.11,15.53 | R14.1 23.66,6.98 23.11,7.53 v23.11,15.53 | R3.1 3.66,6.98 3.11,7.53 v3.11,15.53 | R53.1 103.76,6.98 103.11,7.62 v103.11,15.53 | R64.1 83.66,6.98 83.11,7.53 v83.11,15.53 | R39.1 43.66,6.98 43.11,7.53 v43.11,15.53 | 149.61,70.72 149.32,71.01 149.33,71.02 U$15.P$1 149.33,73.12 149.96,73.75 154.33,73.75 155.33,72.75 U$15.P$2 155.33,70.03 155.29,69.98 156.38,68.9 JP3.2 | 149.61,70.72 149.61,70.73 | 149.61,70.72 C81.-
  Bottom 0.813: v3.11,15.53 v23.11,15.53 v43.11,15.53 v63.11,15.53 v83.11,15.53 v103.11,15.53 v123.11,15.53 v143.11,15.53 153.91,15.53 156.38,17.99 JP3.2
LADC1
  Top 0.406: U3.1 23.18,49.5 20.29,46.6 C4.2
LADC2
  Top 0.406: U6.1 63.18,49.4 60.39,46.6 C30.2
LADC3
  Top 0.406: U9.1 90.18,49.6 87.19,46.6 C50.2
LADC4
  Top 0.406: U12.1 130.18,49.2 127.59,46.6 C70.2
LRCK
  Top 0.305: U15.11 64.3,72.84 63.11,74.03 24.11,74.03 19.11,69.03 19.11,55.02 20.11,54.02 28.51,54.02 29.01,53.52 | U3.10 29.03,53.5 29.01,53.52 | 69.03,53.6 U6.10 | 69.03,53.6 68.61,54.02 29.51,54.02 29.01,53.52 | 96.03,53.7 U9.10 | 96.03,53.7 95.71,54.02 69.46,54.02 69.03,53.6 | U12.10 136.03,53.8 135.81,54.02 96.36,54.02 96.03,53.7
N$1
  Top 0.305: R12.1 28.11,10.03 28.19,9.95 C9.1
  Top 0.406: MIC2.2 31.38,8 32.11,8.72 C9.1
N$2
  Top 0.305: R2.1 8.16,10.08 8.29,9.95 C3.1
  Top 0.406: MIC1.2 11.38,8 12.11,8.72 C3.1
N$3
  Top 0.305: C9.2 33.09,20.1 34.36,21.38 R17.2
  Top 0.406: U2.5 31.85,23.48 32.11,23.22 C9.2
N$4
  Top 0.305: C3.2 13.39,20.1 14.66,21.38 R6.2
  Top 0.406: U1.5 11.85,23.48 12.11,23.22 C3.2
N$5
  Top 0.305: R17.1 34.26,19.67 33.11,18.52 31.61,18.52 30.46,19.67 R22.2 28.06,19.67 28.01,19.72 27.96,19.67 R20.1 24.16,19.67 23.91,19.92 23.91,21.82 23.71,22.02 22.61,22.02 | R18.1 37.36,24.67 37.61,24.42 37.61,19.92 37.36,19.67 R17.1 | 22.61,22.02 R21.1 | C11.1 35.06,15.68 36.11,16.72 R17.1 | C12.+ 22.61,22.02
N$6
  Top 0.305: R11.1 C8.+ 3.73,22 3.91,21.82 3.91,19.92 4.16,19.67 R10.1 8.06,19.67 8.11,19.62 R13.2 10.46,19.67 11.61,18.52 13.11,18.52 14.26,19.67 R6.1 | R7.1 17.36,24.67 17.61,24.42 17.61,20.02 17.26,19.67 R6.1 | C7.1 15.16,15.68 16.11,16.62 R6.1
N$7
  Top 0.305: R18.2 34.96,26.38 34.71,26.12 34.71,24.92 34.46,24.67 R15.1 33.06,24.67 32.98,24.75 U2.6
N$8
  Top 0.305: R15.2 33.11,26.32 32.81,26.02 U2.7 28.71,26.02 27.44,24.75 U2.3
N$9
  Top 0.305: U2.2 22.91,26.02 22.61,26.32 R21.2 R16.2
N$10
  Top 0.305: R7.2 14.96,26.38 14.61,26.02 14.61,25.02 14.26,24.67 R4.1 12.96,24.67 12.88,24.75 U1.6
N$11
  Top 0.406: R5.1 3.96,30.88 4.11,31.02 POT1.P$3
N$12
  Top 0.305: R4.2 12.96,26.38 12.61,26.02 U1.7 8.71,26.02 7.44,24.75 U1.3
N$13
  Top 0.305: U1.2 3.01,26.02 2.66,26.38 R11.2 2.61,29.02 2.51,29.12 2.56,29.17 R5.2
N$14
  Top 0.406: R35.1 63.96,30.88 64.11,31.02 POT4.P$3
N$15
  Top 0.305: R2.2 5.46,11.97 5.11,12.33 C2.+ R1.1
N$16
  Top 0.305: R26.1 68.11,10.12 68.29,9.95 C22.1
  Top 0.406: MIC4.2 71.38,8 72.11,8.72 C22.1
N$17
  Top 0.305: U6.12 68.38,56.35 68.71,56.02 72.41,56.02 72.61,56.23 R49.2
N$18
  Top 0.305: C22.2 73.19,20.1 74.46,21.38 R29.2
  Top 0.406: U4.5 71.85,23.48 72.11,23.22 C22.2
N$19
  Top 0.305: R34.1 C31.+ 63.73,22 63.91,21.82 63.91,19.92 64.16,19.67 R32.1 68.06,19.67 68.11,19.72 R33.2 70.46,19.67 71.61,18.52 73.11,18.52 74.26,19.67 R29.1 | R31.1 77.36,24.67 77.61,24.42 77.61,19.92 77.36,19.67 R29.1 | C24.1 75.16,15.68 76.11,16.62 R29.1
N$20
  Top 0.305: U9.12 95.38,56.35 95.71,56.02 99.31,56.02 99.61,56.32 R74.2
N$21
  Top 0.305: U4.6 72.98,24.75 73.11,24.62 R30.1 74.26,24.67 74.71,25.12 74.71,26.02 75.06,26.38 R31.2
N$22
  Top 0.305: R24.2 32.61,56.23 32.41,56.02 29.01,56.02 28.38,56.65 U3.12
N$23
  Top 0.305: U4.3 67.44,24.75 68.71,26.02 U4.7 72.71,26.02 73.06,26.38 R30.2
N$24
  Top 0.305: U4.2 62.91,26.02 62.61,26.32 R34.2 R35.2 62.61,29.22
N$25
  Top 0.406: R46.1 43.96,30.88 44.11,31.02 POT3.P$3
N$26
  Top 0.305: R26.2 65.66,11.97 65.13,12.5 C21.+ R27.1
N$27
  Top 0.305: R37.1 48.11,10.12 48.29,9.95 C27.1
  Top 0.406: MIC3.2 51.38,8 52.11,8.72 C27.1
N$28
  Top 0.305: C27.2 53.19,20.1 54.46,21.38 R40.2
  Top 0.406: U5.5 51.85,23.48 52.11,23.22 C27.2
N$29
  Top 0.305: R40.1 54.26,19.67 53.11,18.52 51.61,18.52 50.46,19.67 R44.2 47.96,19.67 47.91,19.72 47.86,19.67 R43.1 44.16,19.67 43.91,19.92 43.91,21.82 43.73,22 C32.+ R45.1 | R42.1 57.36,24.67 57.61,24.42 57.61,20.02 57.26,19.67 R40.1 | C29.1 55.16,15.68 56.11,16.62 R40.1
N$30
  Top 0.305: U5.6 52.98,24.75 53.11,24.62 R41.1 54.16,24.67 54.61,25.12 54.61,26.12 54.86,26.38 R42.2
N$31
  Top 0.305: R41.2 53.06,26.38 53.01,26.42 52.61,26.02 U5.7 48.81,26.02 47.54,24.75 U5.3
N$32
  Top 0.305: U5.2 42.91,26.02 42.61,26.32 R45.2 R46.2
N$33
  Top 0.406: R60.1 103.96,30.88 104.11,31.02 POT6.P$3
N$34
  Top 0.305: R37.2 45.56,11.97 45.11,12.43 C26.+ R38.1
N$35
  Top 0.305: U12.12 135.38,56.45 135.81,56.02 139.31,56.02 139.61,56.32 R99.2
N$38
  Top 0.406: 24.11,31.02 POT2.P$3 | 24.11,31.02 | R16.1 23.96,30.88 24.11,31.02
N$39
  Top 0.305: R51.1 108.16,10.08 108.29,9.95 C42.1
  Top 0.406: MIC6.2 111.38,8 112.11,8.72 C42.1
N$40
  Top 0.305: R54.2 114.56,21.38 113.29,20.1 C42.2
  Top 0.406: U7.5 111.75,23.48 112.11,23.12 C42.2
N$41
  Top 0.305: R54.1 114.26,19.67 113.11,18.52 111.61,18.52 110.46,19.67 R58.2 108.11,19.62 108.06,19.67 R57.1 104.16,19.67 103.91,19.92 103.91,21.62 103.63,21.9 C51.+ R59.1 102.61,24.72 | C44.1 114.66,15.68 116.11,17.12 R54.1 | R56.1 117.36,24.67 117.71,24.32 117.71,20.12 117.26,19.67 R54.1
N$42
  Top 0.305: R56.2 114.96,26.38 114.61,26.02 114.61,24.92 114.36,24.67 R55.1 112.96,24.67 112.91,24.62 112.78,24.75 U7.6
N$43
  Top 0.305: U7.3 107.54,24.75 108.81,26.02 U7.7 112.61,26.02 112.96,26.38 R55.2
N$44
  Top 0.305: U7.2 102.91,26.02 102.61,26.32 R59.2 102.61,28.82 102.71,28.92 102.61,29.02 R60.2
N$45
  Top 0.406: R71.1 83.96,30.88 84.11,31.02 POT5.P$3
N$46
  Top 0.305: R51.2 105.56,11.97 105.11,12.43 C41.+ R52.1
N$47
  Top 0.305: R62.1 88.21,10.03 88.29,9.95 C47.1
  Top 0.406: MIC5.2 91.38,8 92.11,8.72 C47.1
N$48
  Top 0.305: C47.2 93.49,20.1 94.76,21.38 R65.2
  Top 0.406: U8.5 91.85,23.48 92.11,23.22 C47.2
N$49
  Top 0.305: R65.1 94.26,19.67 93.11,18.52 91.61,18.52 90.46,19.67 R69.2 88.06,19.67 88.01,19.62 87.96,19.67 R68.1 84.26,19.67 83.91,20.02 83.91,21.82 83.73,22 C52.+ R70.1 | R67.1 97.36,24.67 97.61,24.42 97.61,20.02 97.26,19.67 R65.1 | C49.1 95.16,15.68 96.11,16.62 R65.1
N$50
  Top 0.305: U8.6 92.98,24.75 93.11,24.62 R66.1 94.36,24.67 94.71,25.02 94.71,26.12 94.96,26.38 R67.2
N$51
  Top 0.305: U8.3 87.44,24.75 88.71,26.02 U8.7 92.71,26.02 93.06,26.38 R66.2
N$52
  Top 0.305: U8.2 82.91,26.02 82.61,26.32 R70.2 R71.2 82.61,29.32
N$53
  Top 0.406: R85.1 143.96,30.88 144.11,31.02 POT8.P$3
N$54
  Top 0.305: R62.2 85.66,11.88 85.11,12.43 C46.+ R63.1
N$58
  Top 0.406: C10.1 24.69,36.45 26.05,35.08 POT2.P$1 28.11,33.02 | U2.1 27.38,27.29 29.9,29.82 POT2.P$2 29.11,32.02 28.11,33.02 | 28.11,33.02
N$59
  Top 0.305: R76.1 148.11,10.12 148.29,9.95 C62.1
  Top 0.406: C62.1 152.11,8.72 151.38,8 MIC8.2
N$60
  Top 0.305: C62.2 153.19,20.1 154.46,21.38 R79.2
  Top 0.406: U10.5 151.75,23.48 152.11,23.12 C62.2
N$61
  Top 0.305: C64.1 154.46,15.68 156.11,17.32 R79.1 | R84.1 C71.+ 143.73,22 143.91,21.82 143.91,20.02 144.26,19.67 R82.1 145.16,19.67 145.21,19.62 145.26,19.67 R83.2 150.46,19.67 151.61,18.52 153.61,18.52 154.76,19.67 R79.1 | R79.1 157.36,19.67 157.61,19.92 157.61,24.42 157.36,24.67 R81.1
N$62
  Top 0.305: U10.6 153.08,24.75 153.11,24.72 R80.1 154.16,24.67 154.41,24.92 154.41,26.02 154.76,26.38 R81.2
N$63
  Top 0.305: R80.2 153.11,26.32 152.81,26.02 U10.7 148.91,26.02 147.64,24.75 U10.3
N$64
  Top 0.305: R84.2 142.61,26.42 143.01,26.02 U10.2 | R84.2 142.61,26.12 | R84.2 R85.2
N$66
  Top 0.305: R76.2 145.66,11.97 145.11,12.53 | C61.+ 145.11,12.53 | 145.11,12.53 R77.1
N$67
  Top 0.305: R87.1 128.25,9.95 C67.1
  Top 0.406: MIC7.2 131.38,8.1 132.11,8.83 C67.1
N$68
  Top 0.305: C67.2 133.19,20.1 134.46,21.38 R90.2
  Top 0.406: U11.5 131.85,23.48 132.11,23.22 C67.2
N$69
  Top 0.305: R94.2 R93.1 124.26,19.67 123.91,20.02 123.91,21.82 123.73,22 C72.+ R95.1 | R94.2 128.16,19.67 128.21,19.72 | C69.1 134.46,15.68 136.11,17.32 R90.1 | R90.1 137.26,19.67 137.61,20.02 137.61,24.42 137.36,24.67 R92.1 | R94.2 130.46,19.67 131.61,18.52 133.11,18.52 134.26,19.67 R90.1
N$70
  Top 0.305: U11.6 132.88,24.75 133.01,24.62 133.06,24.67 R91.1 134.16,24.67 134.51,25.02 134.51,26.12 134.76,26.38 R92.2
N$71
  Top 0.305: R91.2 133.06,26.38 133.01,26.42 132.61,26.02 U11.7 128.61,26.02 127.34,24.75 U11.3
N$72
  Top 0.305: R95.2 122.66,26.38 123.01,26.02 U11.2 | R95.2 122.61,26.12 | R95.2 R96.2
N$74
  Top 0.305: R87.2 125.66,11.97 125.13,12.5 C66.+ R88.1
N$76
  Top 0.61: 104.96,71.88 U13.3
  Top 0.813: U15.1 83.38,72.76 84.65,71.48 C82.+ 104.57,71.48 104.96,71.88 104.96,69.68 105.68,68.96 JP4.1 135.68,68.96 135.81,68.83 135.84,68.86 U14.1 135.84,66.69 137.03,65.5 C86.+
N$77
  Top 0.406: U1.1 7.38,27.29 9.9,29.82 POT1.P$2 | POT1.P$1 8.1,33.02 8.11,33.02 9.11,32.02 POT1.P$2 | POT1.P$2 12.1,32.02 16.53,36.45 C4.1
N$78
  Top 0.305: R12.2 25.56,11.97 25.11,12.43 C6.+ R8.1
N$81
  Top 0.406: U4.1 67.38,27.29 69.9,29.82 POT4.P$2 69.11,32.02 68.11,33.02 68.1,33.02 POT4.P$1 66.05,35.08 64.69,36.45 C25.1
N$82
  Top 0.406: POT3.P$1 47.61,33.02 48.61,32.02 49.81,32.02 POT3.P$2 | U5.1 47.38,27.29 49.9,29.82 POT3.P$2 | C30.1 55.53,36.45 51.1,32.02 POT3.P$2
N$83
  Top 0.406: C45.1 93.69,36.45 97.11,33.02 POT6.P$1 108.1,33.02 108.11,33.02 109.11,32.02 POT6.P$2 109.9,29.82 109.11,29.02 107.38,27.29 U7.1
N$84
  Top 0.406: C50.1 85.11,35.02 86.05,34.08 POT5.P$1 88.1,33.02 88.11,33.02 89.11,32.02 POT5.P$2 89.9,29.82 87.38,27.29 U8.1
N$85
  Top 0.406: R96.1 123.96,30.88 124.11,31.02 POT7.P$3
N$86
  Top 0.406: C65.1 134.69,36.45 138.11,33.02 POT8.P$1 148.1,33.02 148.11,33.02 149.11,32.02 POT8.P$2 149.9,29.82 147.38,27.29 U10.1
N$87
  Top 0.406: U11.1 127.38,27.29 129.91,29.83 POT7.P$2 129.11,32.02 128.11,33.02 128.1,33.02 POT7.P$1 126.06,34.07 125.11,35.02 C70.1
RADC1
  Top 0.406: U3.2 23.83,49.05 23.11,48.32 C10.2
RADC2
  Top 0.406: U6.2 63.83,49.05 63.11,48.32 C25.2
RADC3
  Top 0.406: U9.2 90.83,49.05 90.11,48.32 C45.2
RADC4
  Top 0.406: U12.2 130.83,48.85 130.11,48.12 C65.2
REF11  (via drill 0.3)
  Top 0.305: v32.61,47.52 C20.+ | U3.3 24.48,46.85 24.96,46.38 C19.1 27.76,46.38 v27.81,46.32
  Bottom 0.305: v27.81,46.32 31.41,46.32 v32.61,47.52
REF12  (via drill 0.3)
  Top 0.305: U6.3 64.48,46.75 64.86,46.38 C39.1 67.76,46.38 v67.81,46.32 | v72.61,47.52 C40.+
  Bottom 0.305: v67.81,46.32 71.41,46.32 v72.61,47.52
REF13  (via drill 0.3)
  Top 0.305: U9.3 91.48,46.75 91.86,46.38 C59.1 94.86,46.38 v94.91,46.32 | v99.61,47.52 C60.+
  Bottom 0.305: v94.91,46.32 98.41,46.32 v99.61,47.52
REF14  (via drill 0.3)
  Top 0.305: v134.91,46.32 134.86,46.38 133.66,46.38 133.61,46.32 | U12.3 131.48,46.75 131.86,46.38 133.56,46.38 133.61,46.32 | v139.61,47.62 C80.+ | 133.61,46.32 C79.1
  Bottom 0.305: v134.91,46.32 138.31,46.32 v139.61,47.62
REF21
  Top 0.305: U3.4 25.13,47.7 25.41,47.42 28.91,47.42 29.11,47.23 C13.1 29.86,46.38 30.11,46.12 30.11,43.42 29.11,42.42 R23.1 30.96,41.38 31.61,42.02 C14.+
REF22
  Top 0.305: U6.4 65.13,47.6 65.41,47.32 69.01,47.32 69.11,47.23 C33.1 69.86,46.38 70.11,46.12 70.11,43.42 69.11,42.42 R48.1 70.96,41.38 71.61,42.02 C34.+
REF23
  Top 0.305: C54.+ 98.61,41.92 98.06,41.38 R73.1 96.11,42.42 97.11,43.42 97.11,46.12 96.86,46.38 C53.1 96.11,47.23 95.91,47.42 92.31,47.42 92.13,47.6 U9.4
REF24
  Top 0.305: U12.4 132.13,47.7 132.41,47.42 135.91,47.42 136.11,47.23 C73.1 136.86,46.38 137.11,46.12 137.11,43.23 136.11,42.23 R98.1 138.06,41.38 138.61,41.92 C74.+
SCKI
  Top 0.305: U15.15 24.84,72.76 21.11,69.03 21.11,55.42 21.51,55.02 26.01,55.02 26.43,55.45 | 26.43,55.45 U3.15 | 66.43,55.55 U6.15 | 66.43,55.55 65.91,55.02 26.86,55.02 26.43,55.45 | 93.43,55.45 U9.15 | 93.43,55.45 93.01,55.02 66.96,55.02 66.43,55.55 | U12.15 133.43,55.35 133.11,55.02 93.86,55.02 93.43,55.45
VCC  (via drill 0.3, 0.81)
  Top 0.305: U12.5 132.78,48.35 133.11,48.02 138.21,48.02 138.61,47.62 C77.1 140.76,46.38 v141.11,46.02 | R82.2 146.56,21.38 v146.61,21.32 | U10.8 151.78,27.29 152.01,27.52 152.01,28.32 152.36,28.67 C63.1 155.06,28.67 v155.11,28.72 | R93.2 126.56,21.38 v126.61,21.32 | v114.61,28.62 114.56,28.67 C43.1 112.36,28.67 112.11,28.42 112.11,27.52 111.88,27.29 U7.8 | R57.2 106.56,21.38 v106.61,21.32 | U8.8 91.78,27.29 92.01,27.52 92.01,28.32 92.36,28.67 C48.1 94.66,28.67 v94.71,28.62 | R68.2 86.56,21.38 v86.61,21.32 | R32.2 66.56,21.38 v66.61,21.32 | v74.61,28.62 74.56,28.67 C23.1 72.26,28.67 72.01,28.42 72.01,27.52 71.78,27.29 U4.8 | U5.8 51.78,27.29 52.01,27.52 52.01,28.42 52.26,28.67 C28.1 54.56,28.67 v54.61,28.62 | R43.2 46.56,21.38 v46.61,21.32 | R20.2 26.56,21.38 v26.61,21.32 | v34.61,28.62 34.56,28.67 C5.1 32.26,28.67 32.01,28.42 32.01,27.52 31.78,27.29 U2.8 | R10.2 6.56,21.38 v6.61,21.32 | v14.61,28.62 14.56,28.67 C1.1 12.36,28.67 12.11,28.42 12.11,27.52 11.88,27.29 U1.8 | v134.61,28.62 134.56,28.67 C68.1 132.26,28.67 132.01,28.42 132.01,27.52 131.78,27.29 U11.8 | v142.61,47.52 C78.+ | v136.11,37.52 R98.2 | v96.11,37.52 R73.2 | v102.61,47.52 C58.+ | U9.5 92.78,48.35 93.11,48.02 98.21,48.02 98.61,47.62 C57.1 100.76,46.38 v101.11,46.02 | v69.11,37.52 R48.2 | U12.9 135.38,49.35 v135.71,49.02 | U9.9 95.38,49.25 v95.61,49.02 | v75.61,47.52 C38.+ | U6.9 68.38,49.25 v68.61,49.02 | U6.5 65.78,48.35 66.11,48.02 71.21,48.02 71.61,47.62 C37.1 73.76,46.38 v74.11,46.02 | v35.61,47.52 C18.+ | U3.9 28.38,49.25 v28.61,49.02 | v34.11,46.02 33.76,46.38 C17.1 31.61,47.73 31.31,48.02 26.11,48.02 25.78,48.35 U3.5
  Top 0.305: v29.11,37.52 R23.2
  Top 0.813: U14.3 141.96,68.88 143.11,70.03 145.11,70.03 C85.+ v145.11,66.53
  pour $VCC-VDD (isolate 0.762): 0.61,0.53 158.61,0.53 158.61,79.53 138.11,79.53 138.11,51.02 0.61,51.02
VDD  (via drill 0.3, 0.81)
  Top 0.305: U13.2 104.98,74.03 | U12.7 134.08,52.05 v133.11,53.02 | C75.1 135.26,60.67 v135.31,60.62 | C76.+ 132.11,60.12 132.66,60.67 C75.1 | C75.1 134.11,60.62 134.08,60.6 U12.14 | U9.7 94.08,52.05 v93.11,53.02 | U12.16 132.78,56.4 v132.41,56.02 | U9.16 92.78,56.2 v92.61,56.02 | C55.1 94.11,60.62 94.08,60.6 | U9.14 94.08,60.6 | 94.08,60.6 95.23,60.6 v95.31,60.52 | C56.+ 92.13,60.05 92.68,60.6 94.08,60.6 | C36.+ 65.11,60.12 65.66,60.67 C35.1 | C35.1 67.11,60.62 67.08,60.6 U6.14 | C35.1 68.26,60.67 v68.31,60.62 | U6.16 65.78,56.2 v65.61,56.02 | C15.1 27.11,60.62 27.08,60.6 U3.14 | C16.+ 25.11,60.02 25.76,60.67 C15.1 | C15.1 28.26,60.67 v28.31,60.62 | U3.16 25.78,56.2 v25.61,56.02 | U6.7 67.08,52.05 v66.11,53.02 | U3.7 27.08,52.05 v26.11,53.02
  Top 0.61: C84.+ 101.11,74.03 101.13,74
  Top 0.813: 101.13,74 U13.2 | 104.98,74.03 v108.11,74.03
  pour $VCC-VDD (isolate 0.762): 0.61,52.02 137.11,52.02 137.11,79.53 0.61,79.53

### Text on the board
tNames: National Institute of Standards and Technology | VDD | ITC - irst | Universitat Karlsruhe | 9V | Cedrick ROCHET | Claudio BERTOTTI | Julien LEFORT | VCC | Vbat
